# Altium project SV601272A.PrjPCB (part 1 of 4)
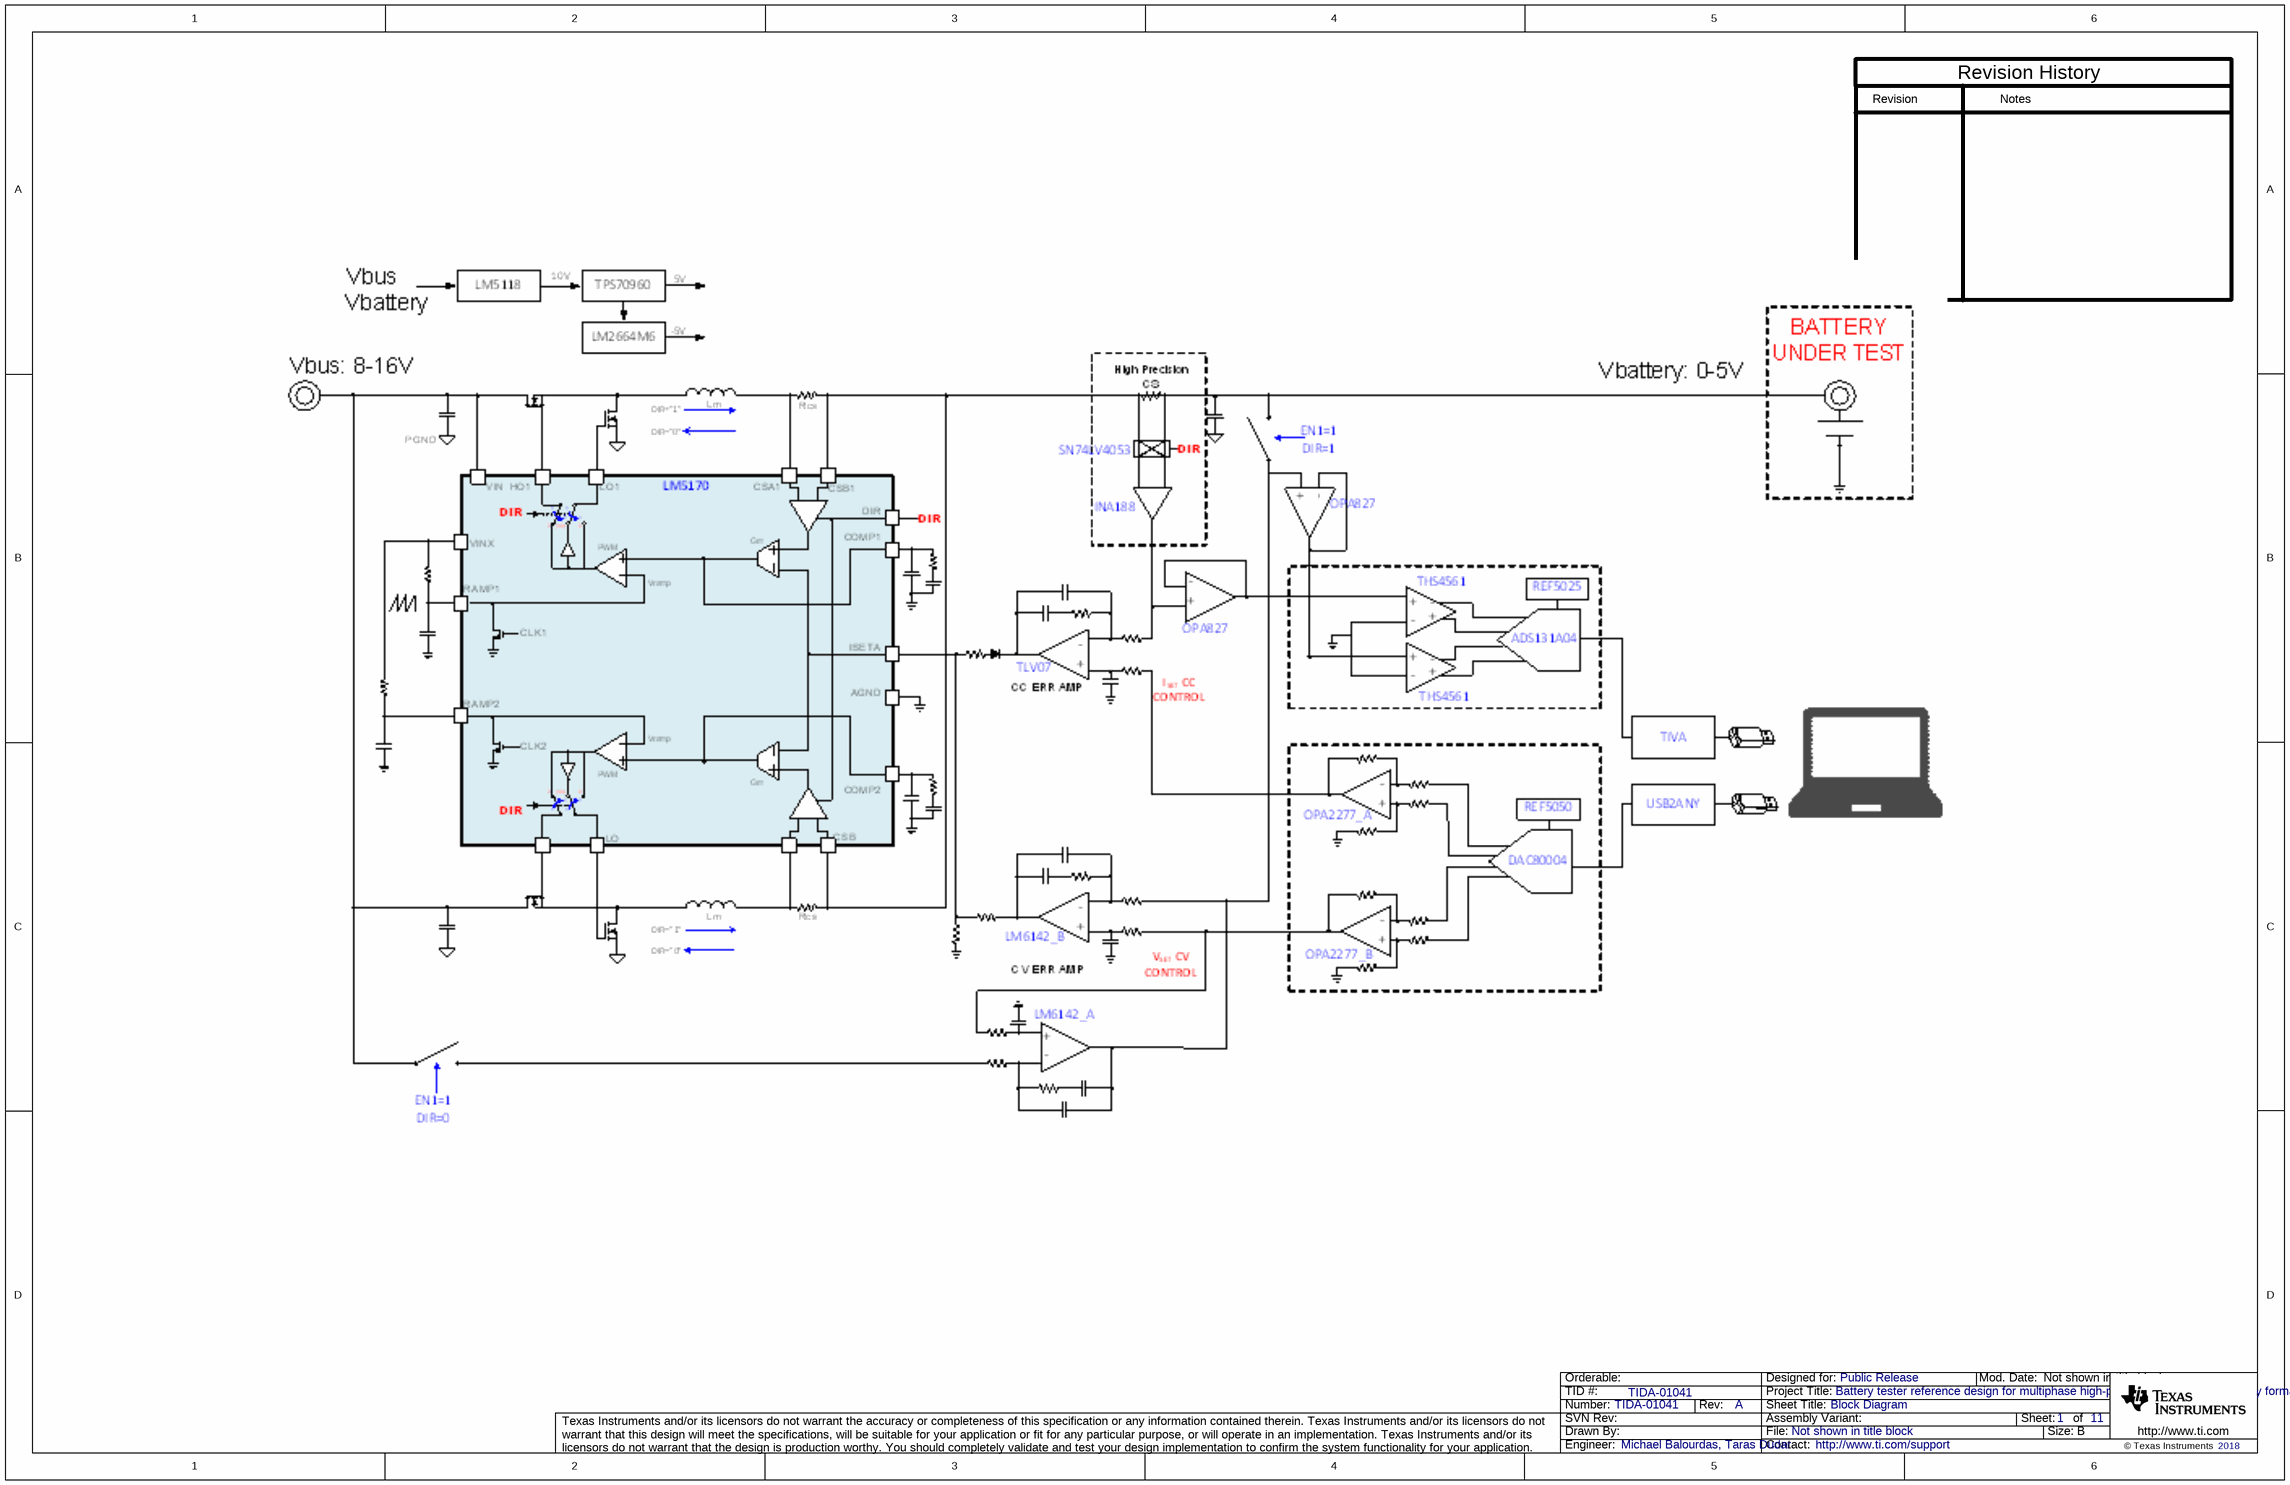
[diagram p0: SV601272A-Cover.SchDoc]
CopyrightYear: 2018; PCB_Layout: Dee Lim; PCB_Rev: A; PRJ_Customer: Public Release; PRJ_Engineer: Michael Balourdas, Taras Dudar; PRJ_Number: TIDA-01041; PRJ_Title: Battery tester reference design for multiphase high-precision 0.5 to 100-A battery formation; SCH_Rev: A; TechSupport: http://www.ti.com/support; TID: TIDA-01041
13 sheets, 552 parts. Net scope: flat (ports and power ports of the same name join across sheets).
Board file: SV601272A.PcbDoc
Sheets:
  SV601272A-Cover.SchDoc
  SV601272A-HW.SchDoc
  SV601272A-Analog.SchDoc
  SV601272A-DAC.SchDoc
  SV601272A-ADC.SchDoc
  SV601272A-TM4C_Main.SchDoc
  SV601272A-TM4C_Power.SchDoc
  SV601272A-Controller2.SchDoc
  SV601272A-Power2 REV2.SchDoc
  SV601272A-Controller1.SchDoc
  SV601272A-Bias.SchDoc
  SV601272A-Power.SchDoc
  SV601272A-Current-Control REV3.SchDoc

## Sheet SV601272A-Cover.SchDoc: Block Diagram
size 431 x 279 mm; Date: Not shown in title block; ApprovedBy: Not shown in title block; CheckedBy: Not shown in title block; Author: Not shown in title block; CompanyName: Not shown in title block; Engineer: Not shown in title block; Organization: Not shown in title block; Address1: Not shown in title block; Address2: Not shown in title block; Address3: Not shown in title block; Address4: Not shown in title block; DocumentNumber: 1; Revision: Use project parameter SCH_Rev; SheetNumber: 1; SheetTotal: 11; PageSetup: Record=PageOptions¦CenterHorizontal=True¦CenterVertical=True¦PrintScale=1.00¦XCorrection=1.00¦YCorrection=1.00¦PrintKind=0¦BorderSize=5000000¦LeftOffset=0¦BottomOffset=0¦Orientation=2¦PaperLength=1000¦PaperWidth=1000¦Scale=100¦PaperSource=15¦PrintQuality=600¦MediaType=1¦DitherType=10¦PaperKind=Letter¦PrintScaleMode=1

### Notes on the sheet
- Revision
- Notes
- Revision History

## Sheet SV601272A-HW.SchDoc: Hardware
size 431 x 279 mm; Date: Not shown in title block; ApprovedBy: Not shown in title block; CheckedBy: Not shown in title block; Author: Not shown in title block; CompanyName: Not shown in title block; Engineer: Not shown in title block; Organization: Not shown in title block; Address1: Not shown in title block; Address2: Not shown in title block; Address3: Not shown in title block; Address4: Not shown in title block; DocumentNumber: 2; Revision: Use project parameter SCH_Rev; SheetNumber: 2; SheetTotal: 11; PageSetup: Record=PageOptions¦CenterHorizontal=True¦CenterVertical=True¦PrintScale=1.00¦XCorrection=1.00¦YCorrection=1.00¦PrintKind=0¦BorderSize=5000000¦LeftOffset=0¦BottomOffset=0¦Orientation=2¦PaperLength=1000¦PaperWidth=1000¦Scale=100¦PaperSource=15¦PrintQuality=600¦MediaType=1¦DitherType=10¦PaperKind=Letter¦PrintScaleMode=1
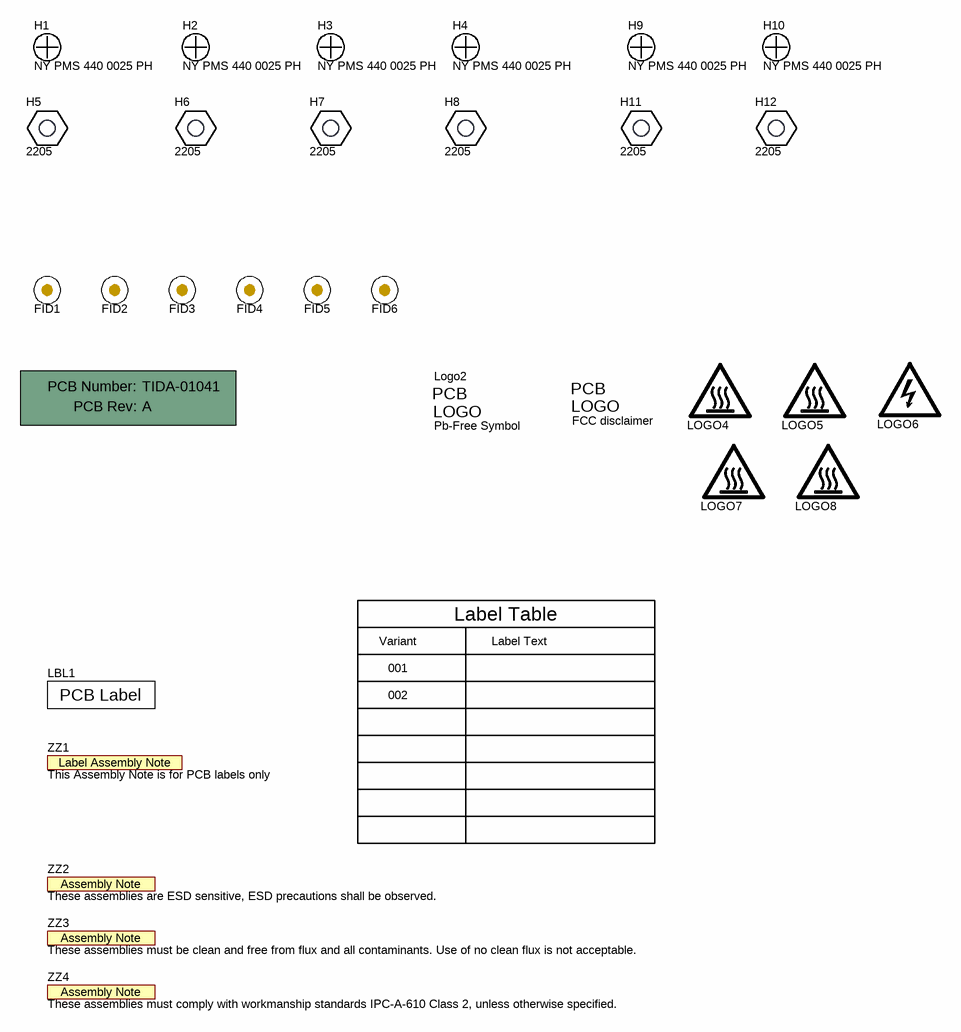
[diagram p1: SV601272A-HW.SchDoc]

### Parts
!PCB1  Printed Circuit Board  (value not drawn)  (mechanical)
FID1  Fiducial  [Fiducial10-20]  (value not drawn)
FID2  Fiducial  [Fiducial10-20]  (value not drawn)
FID3  Fiducial  [Fiducial10-20]  (value not drawn)
FID4  Fiducial  [Fiducial10-20]  (value not drawn)
FID5  Fiducial  [Fiducial10-20]  (value not drawn)
FID6  Fiducial  [Fiducial10-20]  (value not drawn)
H1  NY PMS 440 0025 PH  [NY PMS 440 0025 PH]
H2  NY PMS 440 0025 PH  [NY PMS 440 0025 PH]
H3  NY PMS 440 0025 PH  [NY PMS 440 0025 PH]
H4  NY PMS 440 0025 PH  [NY PMS 440 0025 PH]
H5  2205  [KEYSTONE_2205]
H6  2205  [KEYSTONE_2205]
H7  2205  [KEYSTONE_2205]
H8  2205  [KEYSTONE_2205]
H9  NY PMS 440 0025 PH  [NY PMS 440 0025 PH]
H10  NY PMS 440 0025 PH  [NY PMS 440 0025 PH]
H11  2205  [KEYSTONE_2205]
H12  2205  [KEYSTONE_2205]
LBL1  (no value)  [Label_1250x250]
Logo2  Pb-Free Symbol  [Pb-Free_Overlay_Medium]  (no BOM)
Logo3  FCC disclaimer  [FCC_disclaimer_stacked]  (no BOM)
LOGO4  CAUTION HOT SURFACE  [IEC_HotSurface_Small]  (value not drawn)  (no BOM)
LOGO5  CAUTION HOT SURFACE  [IEC_HotSurface_Small]  (value not drawn)  (no BOM)
LOGO6  DANGER HIGH VOLTAGE  [IEC_HighVoltage_Small]  (value not drawn)  (no BOM)
LOGO7  CAUTION HOT SURFACE  [IEC_HotSurface_Small]  (value not drawn)  (no BOM)
LOGO8  CAUTION HOT SURFACE  [IEC_HotSurface_Small]  (value not drawn)  (no BOM)
ZZ1  This Assembly Note is for PCB labels only  [AssemblyNoteLabel]  (no BOM)
ZZ2  These assemblies are ESD sensitive, ESD precautions shall be observed.  [AssemblyNote]  (no BOM)
ZZ3  These assemblies must be clean and free from flux and all contaminants. Use of no clean flux is not acceptable.  [AssemblyNote]  (no BOM)
ZZ4  These assemblies must comply with workmanship standards IPC-A-610 Class 2, unless otherwise specified.  [AssemblyNote]  (no BOM)

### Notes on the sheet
- Variant
- Label Table
- Label Text
- 001
- 002

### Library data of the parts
!PCB1 = PCB: Manufacturer: Any; PartNumber: TIDA-01041; SymbolCreator: a0412235
FID1-FID6 = Fiducial: Fiducial mark.  There is nothing to buy or mount.; SymbolCreator: codlsc
H1-H4 H9 H10 = NY PMS 440 0025 PH: Machine Screw, Round, #4-40 x 1/4, Nylon, Philips panhead; Manufacturer: B&F Fastener Supply; CompType: Hardware; SymbolCreator: codlsc; U/M: EA
H5-H8 H11 H12 = 2205: Standoff, Hex, 1"L #4-40 Aluminum; Manufacturer: Keystone; SymbolCreator: a0412235
LBL1 = THT-13-457-10: Thermal Transfer Printable Labels, 1.250" W x 0.250" H - 10,000 per roll; Manufacturer: Brady; SymbolCreator: a0412235; CompType: Label
Logo2 = Pb-Free: SymbolCreator: a0412235
Logo3 = FCC_disclaimer: SymbolCreator: codlsc
LOGO4 LOGO5 LOGO7 LOGO8 = IEC_HotSurface: IEC 61010-1 Hot Surface Warning; SymbolCreator: a0412235
LOGO6 = IEC_HighVoltage: IEC 61010-1 High Voltage Warning; SymbolCreator: a0412235
ZZ1 = AssemblyNoteLabel: SymbolCreator: a0412235
ZZ2-ZZ4 = AssemblyNote: SymbolCreator: codlsc

## Sheet SV601272A-Analog.SchDoc: Analog Loop Controller
size 431 x 279 mm; Date: Not shown in title block; ApprovedBy: Not shown in title block; CheckedBy: Not shown in title block; Author: Not shown in title block; CompanyName: Not shown in title block; Engineer: Not shown in title block; Organization: Not shown in title block; Address1: Not shown in title block; Address2: Not shown in title block; Address3: Not shown in title block; Address4: Not shown in title block; DocumentNumber: 7; Revision: Use project parameter SCH_Rev; SheetNumber: 7; SheetTotal: 11; PageSetup: Record=PageOptions¦CenterHorizontal=True¦CenterVertical=True¦PrintScale=1.00¦XCorrection=1.00¦YCorrection=1.00¦PrintKind=0¦BorderSize=5000000¦LeftOffset=0¦BottomOffset=0¦Orientation=2¦PaperLength=1000¦PaperWidth=1000¦Scale=100¦PaperSource=15¦PrintQuality=600¦MediaType=1¦DitherType=10¦PaperKind=Letter¦PrintScaleMode=1
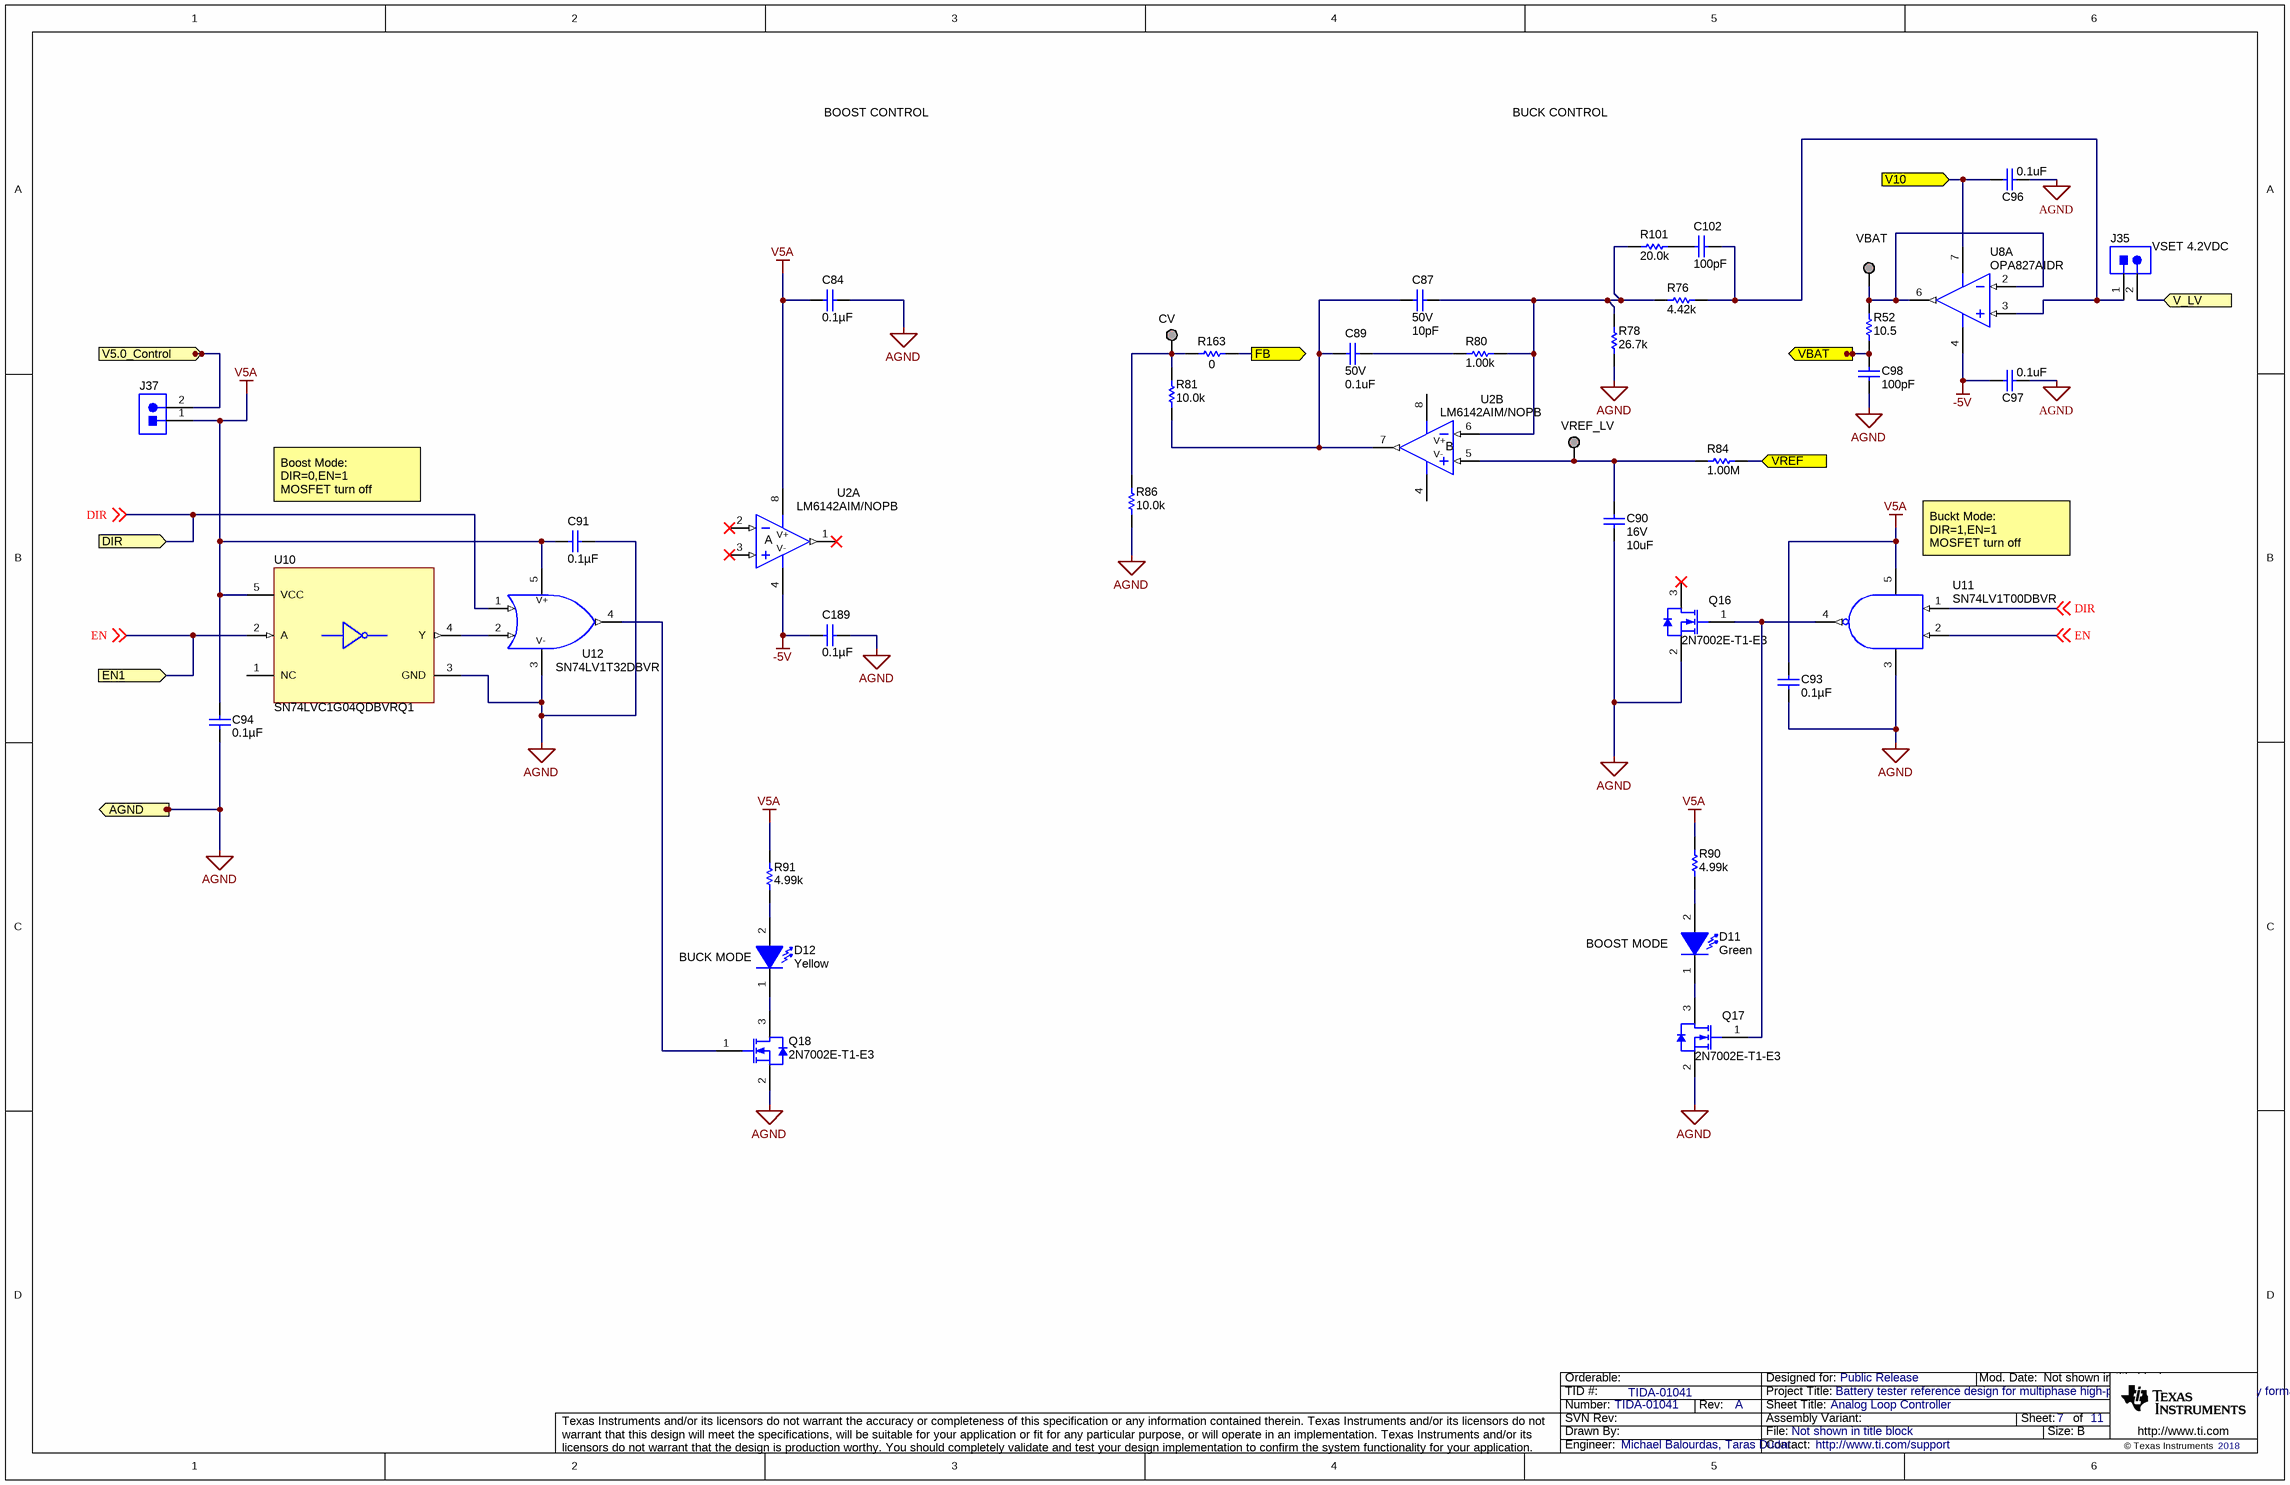
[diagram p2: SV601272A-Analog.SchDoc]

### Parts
C84  ValueDisplayed: 0.1µF  [0603L]  (hidden comment: GRM188R72A104KA35D)
C87  VDC_V: 50V  ValueDisplayed: 10pF  [0603]  (hidden comment: C0603C100J5GACTU)
C89  VDC_V: 50V  ValueDisplayed: 0.1uF  [0603]  (hidden comment: C1608X5R1H104K080AA)
C90  VDC_V: 16V  ValueDisplayed: 10uF  [0603]  (hidden comment: EMK107BBJ106MA-T)
C91  ValueDisplayed: 0.1µF  [0603L]  (hidden comment: GRM188R72A104KA35D)
C93  ValueDisplayed: 0.1µF  [0603L]  (hidden comment: GRM188R72A104KA35D)
C94  ValueDisplayed: 0.1µF  [0603L]  (hidden comment: GRM188R72A104KA35D)
C96  ValueDisplayed: 0.1uF  [0603]  (hidden comment: Capacitor)
C97  ValueDisplayed: 0.1uF  [0603]  (hidden comment: Capacitor)
C98  ValueDisplayed: 100pF  [0603L]  (hidden comment: Capacitor)
C102  ValueDisplayed: 100pF  [0603L]  (hidden comment: C0603C101J5GACTU)
C189  ValueDisplayed: 0.1µF  [0603L]  (hidden comment: GRM188R72A104KA35D)
CV  Pogo Pad  [PogoPad]  (value not drawn)  (no BOM)
D11  value Green  [WL-SMCW_GREEN]  (hidden comment: 150060VS75000)
D12  value Yellow  [WL-SMCW_YELLOW]  (hidden comment: 150060YS75000)
J35  HTSW-102-07-G-S  [Samtec_HTSW-102-07-G-S]  (value not drawn)
J37  HTSW-102-07-G-S  [Samtec_HTSW-102-07-G-S]  (value not drawn)
Q16  2N7002E-T1-E3  [SOT-23]
Q17  2N7002E-T1-E3  [SOT-23]
Q18  2N7002E-T1-E3  [SOT-23]
R52  ValueDisplayed: 10.5  [0603]  (hidden comment: RC0603FR-0710R5L)
R76  ValueDisplayed: 4.42k  [0603L]  (hidden comment: CRCW06034K42FKEA)
R78  ValueDisplayed: 26.7k  [0603L]  (hidden comment: CRCW060326K7FKEA)
R80  ValueDisplayed: 1.00k  [0603]  (hidden comment: CRCW06031K00FKEA)
R81  ValueDisplayed: 10.0k  [0603L]  (hidden comment: CRCW060310K0FKEA)
R84  ValueDisplayed: 1.00M  [0603]  (hidden comment: MCT06030C1004FP500)
R86  ValueDisplayed: 10.0k  [0603L]  (hidden comment: CRCW060310K0FKEA)
R90  ValueDisplayed: 4.99k  [0603L]  (hidden comment: CRCW06034K99FKEA)
R91  ValueDisplayed: 4.99k  [0603L]  (hidden comment: CRCW06034K99FKEA)
R101  ValueDisplayed: 20.0k  [0603L]  (hidden comment: CRCW060320K0FKEA)
R163  ValueDisplayed: 0  [0603]  (hidden comment: Resistor)
U2  LM6142AIM/NOPB  [D0008A_N]  (parts A,B of 2)
U8  OPA827AIDR  [D0008A_L]  (part A of 2)
U10  SN74LVC1G04QDBVRQ1  [DBV0005A_N]
U11  SN74LV1T00DBVR  [DBV0005A_N]
U12  SN74LV1T32DBVR  [DBV0005A_N]
VBAT  Pogo Pad  [PogoPad]  (value not drawn)  (no BOM)
VREF_LV  Pogo Pad  [PogoPad]  (value not drawn)  (no BOM)

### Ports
AGND, DIR, EN1, FB, V5.0_Control, V10, V_LV, VBAT, VREF

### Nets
-5V: C97.1 C189.1 U2.4(V-) U8.4(V-)
AGND: C84.2 C90.2 C91.1 C93.2 C94.1 C96.2 C97.2 C98.2 C189.2 Q16.2(S) Q17.2(S) Q18.2(S) R78.1 R86.2 U10.3(GND) U11.3(GND) U12.3(GND) ; port AGND
V5A: C84.1 C91.2 C93.1 C94.2 J37.1 R90.1 R91.1 U2.8(V+) U10.5(VCC) U11.5(VCC) U12.5(VCC)
V_LV: J35.2 ; port V_LV
VCC: C96.1 U8.7(V+) ; port V10
DIR: U11.1(A) U12.1(A) ; off-sheet DIR, port DIR
EN: U10.2(A) U11.2(B) ; off-sheet EN, port EN1
FB: R163.2 ; port FB
V5.0_Control: J37.2 ; port V5.0_Control
VBAT: C98.1 R52.1 ; port VBAT
VREF: R84.2 ; port VREF
NetC87_1: C87.1 R76.2 R78.2 R80.2 R101.2 U2.6(IN-)
NetC87_2: C87.2 C89.2 R81.2 U2.7(OUT)
NetC89_1: C89.1 R80.1
NetC90_1: C90.1 R84.1 U2.5(IN+) VREF_LV.1
NetC102_1: C102.1 J35.1 R76.1 U8.3(IN+)
NetC102_2: C102.2 R101.1
NetCV_1: CV.1 R81.1 R86.1 R163.1
NetD11_1: D11.1(K) Q17.3(D)
NetD11_2: D11.2(A) R90.2
NetD12_1: D12.1(K) Q18.3(D)
NetD12_2: D12.2(A) R91.2
NetQ16_1: Q16.1(G) Q17.1(G) U11.4(Y)
NetQ18_1: Q18.1(G) U12.4(Y)
NetR52_2: R52.2 U8.2(IN-) U8.6(OUT) VBAT.1
NetU10_4: U10.4(Y) U12.2(B)

Not connected (* = marked no-connect by the designer): Q16 3(D)*; U2 1(OUT)* 2(IN-)* 3(IN+)*; U10 1(NC)

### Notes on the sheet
- BOOST CONTROL
- BUCK CONTROL
- (near J35) VSET 4.2VDC
- Boost Mode: DIR=0,EN=1
  MOSFET turn off
- (near U11) Buckt Mode: DIR=1,EN=1
  MOSFET turn off
- (near D12) BUCK MODE
- (near D11) BOOST MODE

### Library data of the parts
C84 C91 C93 C94 C189 = GRM188R72A104KA35D: CAP, CERM, 0.1 µF, 100 V, +/- 10%, X7R, 0603; Manufacturer: MuRata; Polarized: N; CompType: Capacitor; Value: 0.1uF; U/M: EA; Cap_F: 0.0000001; Tolerance_%: 10; Value1: Unknown; VDC_V: 100; Value2: 100V; TaMin_C: -55; TaMax_C: 125; Cap_Case: 0603; AEC Category: Q200
C87 = CMP-0006839-4: CAP, CERM, 10 pF, 50 V, +/- 5%, C0G/NP0, 0603; Manufacturer: Kemet; TaMin_C: -55°C; Polarized: N; SizeAreaWB_mm2: 4.68; Value1: Unknown; U/M: EA; Value: 10pF; TaMax_C: 125°C; SizeZ_mm: 1; SizeX_mm: 1.6; SizeY_mm: 0.8; SizeArea_mm2: 1.28; CompType: Capacitor; AEC Category: Q200
C89 = CMP-0007010-5: CAP, CERM, 0.1 uF, 50 V, +/- 10%, X5R, 0603; Manufacturer: TDK; TaMin_C: -55°C; ESR_ohm: 0.0296; Polarized: N; SizeAreaWB_mm2: 4.68; Value1: 0.0296 ohm; U/M: EA; Value: 0.1uF; TaMax_C: 85°C; SizeZ_mm: 1; SizeX_mm: 1.6; SizeY_mm: 0.8; SizeArea_mm2: 1.28; CompType: Capacitor; Cap_F: 100nF; IRMS_A: 9.7199dA; AEC Category: Q200
C90 = CMP-0007122-5: CAP, CERM, 10 uF, 16 V, +/- 20%, X5R, 0603; Manufacturer: Taiyo Yuden; TaMin_C: -55°C; Polarized: N; SizeAreaWB_mm2: 4.68; Value1: Unknown; U/M: EA; Value: 10uF; TaMax_C: 85°C; SizeZ_mm: 1; SizeX_mm: 1.6; SizeY_mm: 0.8; SizeArea_mm2: 1.28; CompType: Capacitor; Cap_F: 10µF; AEC Category: Q200
C96 C97 = CMP-0006752-5: CAP, CERM, 0.1 uF, 25 V, +/- 5%, X7R, 0603; PartNumber: 06033C104JAT2A; Manufacturer: AVX; Polarized: N; Value: 0.1uF; U/M: EA; Cap_F: 100nF; ESR_ohm: 0.05; Value1: 0.05 ohm; VDC_V: 25V; TaMin_C: -55°C; TaMax_C: 125°C; AEC Category: Q200; SizeArea_mm2: 1.28; SizeAreaWB_mm2: 4.68; SizeX_mm: 1.6; SizeY_mm: 0.8; SizeZ_mm: 1
C98 = CMP-0006841-4: CAP, CERM, 100 pF, 50 V, +/- 5%, C0G/NP0, 0603; PartNumber: C0603C101J5GACTU; Manufacturer: Kemet; Polarized: N; Value: 100pF; U/M: EA; Value1: Unknown; VDC_V: 50V; TaMin_C: -55°C; TaMax_C: 125°C; Cap_Case: 0603; AEC Category: Q200; SizeArea_mm2: 1.28; SizeAreaWB_mm2: 4.68; SizeX_mm: 1.6; SizeY_mm: 0.8; SizeZ_mm: 1
C102 = C0603C101J5GACTU: CAP, CERM, 100 pF, 50 V, +/- 5%, C0G/NP0, 0603; Manufacturer: Kemet; Polarized: N; CompType: Capacitor; Value: 100pF; U/M: EA; Cap_F: 0.0000000001; Tolerance_%: 5; Value1: Unknown; VDC_V: 50; Value2: 50V; TaMin_C: -55; TaMax_C: 125; Cap_Case: 0603
CV VBAT VREF_LV = PogoPad: Pad for Pogo Pin Connector; SymbolCreator: codlsc
D11 = 150060VS75000: LED, Green, SMD; Manufacturer: Wurth Elektronik; Type: AlInGaP; Vf_V: 2; Value2: 2V; Io_A: 0.02; Value1: W; U/M: EA
D12 = 150060YS75000: LED, Yellow, SMD; Manufacturer: Wurth Elektronik; Type: AlInGaP; Vf_V: 2; Value2: 2V; Io_A: 0.02; Value1: W; U/M: EA
J35 J37 = HTSW-102-07-G-S: Header, 100mil, 2x1, Gold, TH; Manufacturer: Samtec; SymbolCreator: a0412235; U/M: EA
Q16-Q18 = 2N7002E-T1-E3: MOSFET, N-CH, 60 V, 0.24 A, SOT-23; Manufacturer: Vishay-Siliconix; Alternate Manufacturer: None; U/M: EA; ChType: N; Value: 60V; VdsMax_V: 60; Value1: 1.8 ohm; Rdson45_ohm: 1.8; Value2: 0.4 nC; QgTyp_nC: 0.4; Vgs_V: 20; IdsMax_A: 0.24
R52 = CMP-0022749-2: RES, 10.5, 1%, 0.1 W, 0603; Manufacturer: Yageo America; Power_W: 100mW; TempCo: 200 ppm/C; Value_Code: 10R5; U/M: EA; Value: 10.5; EIA_Code: E96; SizeX_mm: 1.6; SizeY_mm: 0.8; SizeZ_mm: 1; Value2: 0.1W; SizeArea_mm2: 1.28; CompType: Resistor; VDC_V: 150V; AEC Category: Q200
R76 = CRCW06034K42FKEA: RES, 4.42 k, 1%, 0.1 W, 0603; Manufacturer: Vishay-Dale; CompType: Resistor; Value: 4.42k; Res_ohm: 4420; Value_Code: 4k42; Tolerance_%: 1; Power_W: 0.1; Value2: 0.1W; VDC_V: 75; TempCo: 100 ppm/C; EIA_Code: E96; U/M: EA; AEC Category: Q200; SizeArea_mm2: 1.28; SizeX_mm: 1.6; SizeY_mm: 0.8
R78 = CRCW060326K7FKEA: RES, 26.7 k, 1%, 0.1 W, 0603; Manufacturer: Vishay-Dale; CompType: Resistor; Value: 26.7k; Res_ohm: 26700; Value_Code: 26k7; Tolerance_%: 1; Power_W: 0.1; Value2: 0.1W; VDC_V: 75; TempCo: 100 ppm/C; EIA_Code: E96; U/M: EA; AEC Category: Q200; SizeArea_mm2: 1.28; SizeX_mm: 1.6; SizeY_mm: 0.8
R80 = CMP-0022109-5: RES, 1.00 k, 1%, 0.1 W, AEC-Q200 Grade 0, 0603; Manufacturer: Vishay-Dale; Power_W: 100mW; TempCo: 100 ppm/C; Value_Code: 1k00; Value: 1.00k; EIA_Code: E96; Res_ohm: 1k; SizeX_mm: 1.6; SizeY_mm: 0.8; SizeZ_mm: 1; Value2: 0.1W; SizeArea_mm2: 1.28; CompType: Resistor; AEC Qualified: Y; VDC_V: 75V; AEC Category: Q200; AEC Grade: 0
R81 R86 = CRCW060310K0FKEA: RES, 10.0 k, 1%, 0.1 W, 0603; Manufacturer: Vishay-Dale; CompType: Resistor; Value: 10.0k; Res_ohm: 10000; Value_Code: 10k0; Tolerance_%: 1; Power_W: 0.1; Value2: 0.1W; VDC_V: 75; TempCo: 100 ppm/C; EIA_Code: E96; U/M: EA
R84 = CMP-0022731-2: RES, 1.00 M, 1%, 0.125 W, 0603; Manufacturer: Vishay/Beyschlag; Power_W: 125mW; TempCo: 50 ppm/C; Value_Code: 1M00; U/M: EA; Value: 1.00Meg; EIA_Code: E96; Res_ohm: 1M; SizeX_mm: 1.6; SizeY_mm: 0.8; SizeZ_mm: 1; Value2: 0.125W; SizeArea_mm2: 1.28; CompType: Resistor; AEC Qualified: N; VDC_V: 75V; AEC Category: Q200
R90 R91 = CRCW06034K99FKEA: RES, 4.99 k, 1%, 0.1 W, 0603; Manufacturer: Vishay-Dale; CompType: Resistor; Value: 4.99k; Res_ohm: 4990; Value_Code: 4k99; Tolerance_%: 1; Power_W: 0.1; Value2: 0.1W; VDC_V: 75; TempCo: 100 ppm/C; EIA_Code: E96; U/M: EA
R101 = CRCW060320K0FKEA: RES, 20.0 k, 1%, 0.1 W, 0603; Manufacturer: Vishay-Dale; CompType: Resistor; Value: 20.0k; Res_ohm: 20000; Value_Code: 20k0; Tolerance_%: 1; Power_W: 0.1; Value2: 0.1W; VDC_V: 75; TempCo: 100 ppm/C; EIA_Code: E96; U/M: EA; SizeArea_mm2: 1.28; SizeX_mm: 1.6; SizeY_mm: 0.8; AEC Category: Q200
R163 = CMP-0025874-3: RES, 0, 5%, 0.1 W, 0603; PartNumber: ERJ-3GEY0R00V; Manufacturer: Panasonic; Value: 0; Value_Code: 0000; Power_W: 100mW; Value2: 0.1W; VDC_V: 50V; TempCo: 600 ppm/C; EIA_Code: E24; U/M: EA; AEC Category: Q200; SizeArea_mm2: 1.28; SizeX_mm: 1.6; SizeY_mm: 0.8; SizeZ_mm: 1
U2 = LM6142AIM: 17MHz Rail-to-Rail Input and Output Op Amp, D0008A; Manufacturer: Texas Instruments; CompType: OpAmp IC
U8 = CMP-0041267-2: Low-Noise, High-Precision, JFET-Input Operational Amplifier, 8 to 36 V, -40 to 125 degC, 8-pin SOIC (D8), Green (RoHS & no Sb/Br); Manufacturer: Texas Instruments; Vmax(V): 36; GBW(Typ)(MHz): 22; Vmin(V): 8; Iq per channel(Max)(mA): 5.2; SubFamily: Audio Operational Amplifier; Number of Channels: 1; Vn at Flatband(Typ)(nV/rtHz): 4
U10 = SN74LVC1G04QDBVRQ1: Single Inverter Gate, DBV0005A; Manufacturer: Texas Instruments; SymbolCreator: a0411947; CompType: IC; U/M: EA
U11 = SN74LV1T00DBVR: Single Power Supply 2-Input Positive NAND Gate CMOS Logic Level Shifter, DBV0005A; Manufacturer: Texas Instruments; SymbolCreator: a0411947; CompType: IC; U/M: EA
U12 = SN74LV1T32DBVR: Single Power Supply 2-Input Positive OR Gate CMOS Logic Level Shifter, DBV0005A; Manufacturer: Texas Instruments; SymbolCreator: a0411947; CompType: IC; U/M: EA

## Sheet SV601272A-DAC.SchDoc
size 431 x 279 mm; Date: Not shown in title block; ApprovedBy: Not shown in title block; CheckedBy: Not shown in title block; Author: Not shown in title block; CompanyName: Not shown in title block; Engineer: Not shown in title block; Organization: Not shown in title block; Address1: Not shown in title block; Address2: Not shown in title block; Address3: Not shown in title block; Address4: Not shown in title block; DocumentNumber: 8; Revision: Use project parameter SCH_Rev; SheetNumber: 8; SheetTotal: 11; PageSetup: Record=PageOptions¦CenterHorizontal=True¦CenterVertical=True¦PrintScale=1.00¦XCorrection=1.00¦YCorrection=1.00¦PrintKind=0¦BorderSize=5000000¦LeftOffset=0¦BottomOffset=0¦Orientation=2¦PaperLength=1000¦PaperWidth=1000¦Scale=100¦PaperSource=15¦PrintQuality=600¦MediaType=1¦DitherType=10¦PaperKind=Letter¦PrintScaleMode=1
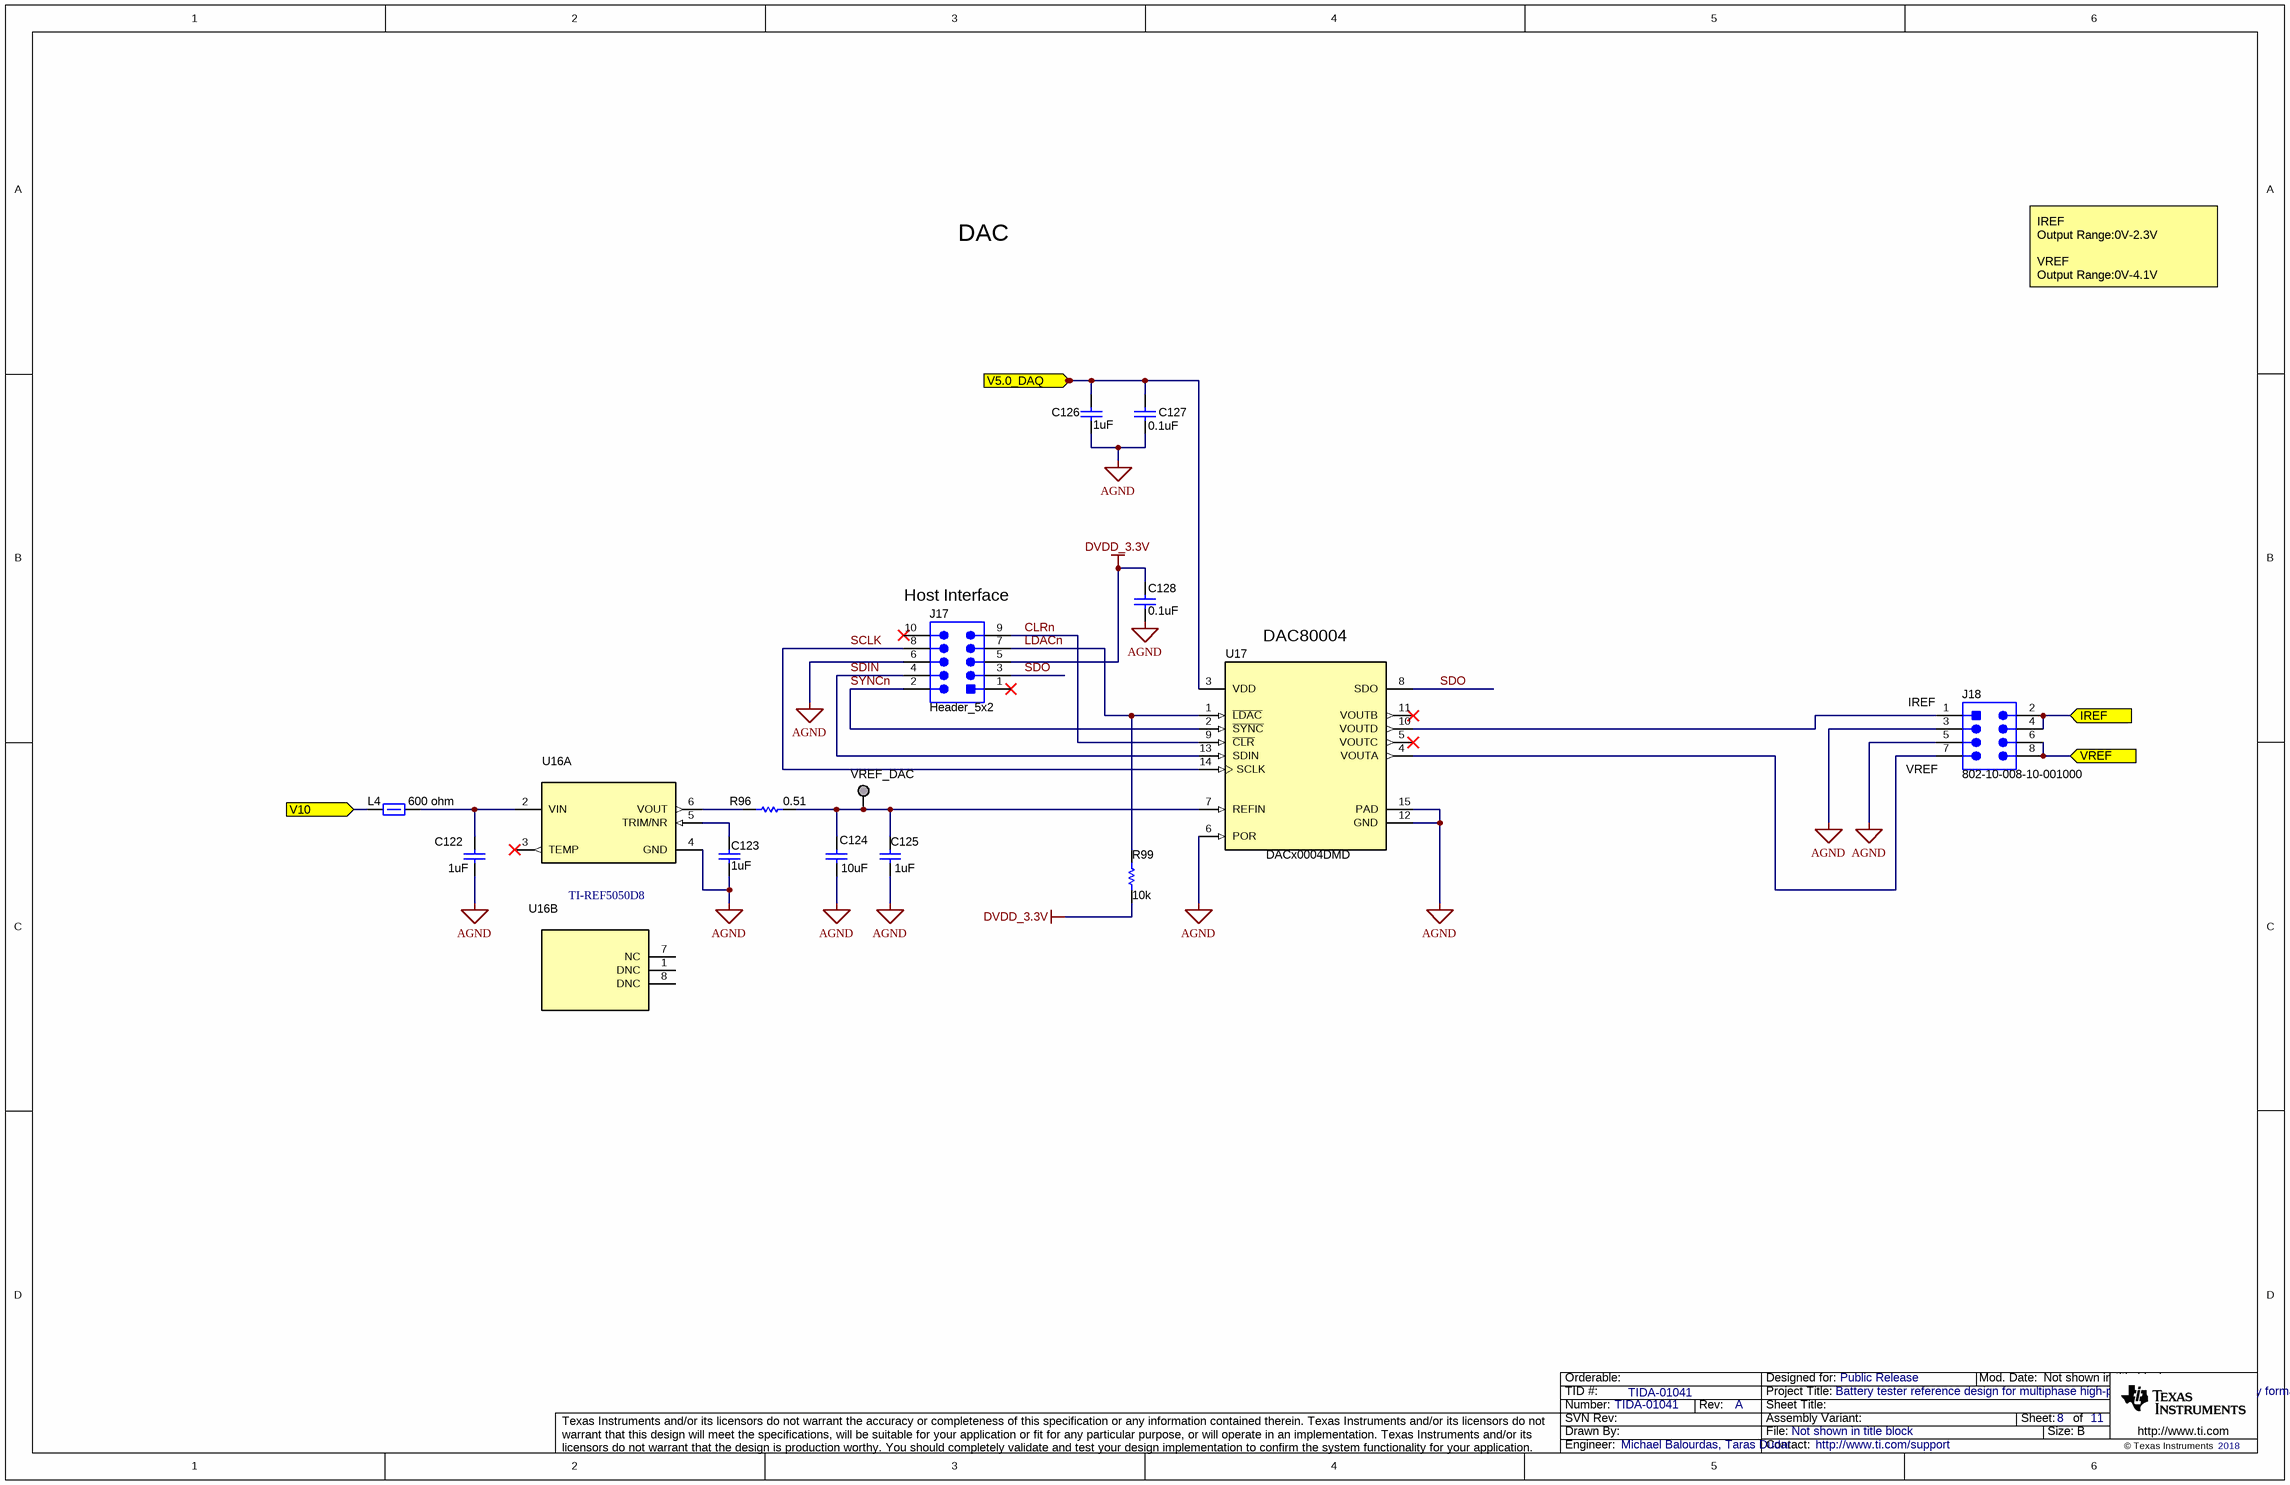
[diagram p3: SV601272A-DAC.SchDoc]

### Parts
C122  ValueDisplayed: 1uF  [1206]  (hidden comment: Capacitor)
C123  ValueDisplayed: 1uF  [1206]  (hidden comment: Capacitor)
C124  ValueDisplayed: 10uF  [0805_HV]  (hidden comment: Capacitor)
C125  ValueDisplayed: 1uF  [1206]  (hidden comment: Capacitor)
C126  ValueDisplayed: 1uF  [1206]  (hidden comment: Capacitor)
C127  ValueDisplayed: 0.1uF  [0603]  (hidden comment: Capacitor)
C128  ValueDisplayed: 0.1uF  [0603]  (hidden comment: Capacitor)
J17  Header_5x2  [Assman_AWHW-10G-0x02-T]
J18  802-10-008-10-001000  [Mill-Max_802-10-008-10-001000]
L4  value 600 ohm  [0603]  (hidden comment: Ferrite_Bead)
R96  ValueDisplayed: 0.51  [0603]  (hidden comment: Resistor)
R99  ValueDisplayed: 10k  [0603]  (hidden comment: Resistor)
U16  TI-REF5050D8  [D0008A_N]  (parts A,B of 2)
U17  DACx0004DMD  [DMD0014A]
VREF_DAC  Pogo Pad  [PogoPad]  (value not drawn)  (no BOM)

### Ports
IREF, V5.0_DAQ, V10, VREF

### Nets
AGND: C122.2 C123.2 C124.2 C125.2 C126.2 C127.2 C128.2 J17.6 J18.3 J18.5 U16.4(GND) U17.6(POR) U17.12(GND) U17.15(PAD)
AVDD: C126.1 C127.1 U17.3(VDD) ; port V5.0_DAQ
DVDD_3.3V: C128.1 J17.5 R99.1
VCC: L4.1 ; port V10
CLRn: J17.9 U17.9(~{CLR})
IREF: J18.2 J18.4 ; port IREF
LDACn: J17.7 R99.2 U17.1(~{LDAC})
SCLK: J17.8 U17.14(SCLK)
SDIN: J17.4 U17.13(SDIN)
SDO: J17.3 U17.8(SDO)
SYNCn: J17.2 U17.2(~{SYNC})
VREF: J18.6 J18.8 ; port VREF
NetC122_1: C122.1 L4.2 U16.2(VIN)
NetC123_1: C123.1 U16.5(TRIM/NR)
NetC124_1: C124.1 C125.1 R96.2 U17.7(REFIN) VREF_DAC.1
NetJ18_1: J18.1 U17.10(VOUTD)
NetJ18_7: J18.7 U17.4(VOUTA)
NetR96_1: R96.1 U16.6(VOUT)

Not connected (* = marked no-connect by the designer): J17 1* 10*; U16 1(DNC) 3(TEMP)* 7(NC) 8(DNC); U17 5(VOUTC)* 11(VOUTB)*

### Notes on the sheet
- DAC
- IREF
  Output Range:0V-2.3V
  VREF
  Output Range:0V-4.1V
- (near J17) Host Interface
- (near U17) DAC80004
- (near J18) IREF
- (near J18) VREF

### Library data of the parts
C122 C123 C125 C126 = CMP-0008509-2: CAP, CERM, 1 uF, 25 V, +/- 10%, X7R, 1206; PartNumber: 12063C105KAT2A; Manufacturer: AVX; Polarized: N; Value: 1uF; U/M: EA; Cap_F: 1µF; ESR_ohm: 0.013; Value1: 0.013 ohm; VDC_V: 25V; TaMin_C: -55°C; TaMax_C: 125°C; SizeArea_mm2: 5.12; SizeAreaWB_mm2: 10.92; SizeX_mm: 3.2; SizeY_mm: 1.6; SizeZ_mm: 1.35; AEC Category: Q200
C124 = CMP-0008273-1: CAP, CERM, 10 uF, 35 V, +/- 10%, X6S, 0805; PartNumber: GRM21BC8YA106KE11L; Manufacturer: MuRata; Polarized: N; Value: 10uF; U/M: EA; Cap_F: 10µF; Value1: Unknown; VDC_V: 35V; TaMin_C: -55°C; TaMax_C: 105°C; Cap_Case: 0805; SizeArea_mm2: 2.5; SizeAreaWB_mm2: 6.75; SizeX_mm: 2; SizeY_mm: 1.25; SizeZ_mm: 1.45; AEC Category: Q200
C127 C128 = CMP-0006857-4: CAP, CERM, 0.1 uF, 16 V, +/- 5%, X7R, 0603; PartNumber: C0603C104J4RACTU; Manufacturer: Kemet; Polarized: N; Value: 0.1uF; U/M: EA; Cap_F: 100nF; Value1: Unknown; VDC_V: 16V; TaMin_C: -55°C; TaMax_C: 125°C; SizeArea_mm2: 1.28; SizeAreaWB_mm2: 4.68; SizeX_mm: 1.6; SizeY_mm: 0.8; SizeZ_mm: 1; AEC Category: Q200
J17 = CMP-0075161-1: Header(Shrouded), 2.54mm, 5x2, Gold, TH; PartNumber: AWHW-10G-0202-T; Manufacturer: Assman WSW; Pitch_mm: 2.54; Gender: Male; Shrouded: Y; Row_Count: 2; CNHeader: False; Green_Lifecycle: Active; Green_REACh: Passed
J18 = CMP-0055096-1: Header, 2.54 mm, 4x2, Gold, TH; Manufacturer: Mill-Max; CNHeader: TRUE; Shrouded: N; Gender: Male; Row_Count: 2; RowSpacing_mm: 2.54; CT: FALSE
L4 = CMP-0003197-2: Ferrite Bead, 600 ohm @ 100 MHz, 1 A, 0603; PartNumber: 742792651; Manufacturer: Wurth Elektronik; Imax_A: 1A; DCR_ohm: 2d; Value1: 0.2 ohm; ZTyp@100MHz_Ohm: 600; Ztyp@1GHz_Ohm: 257.548; SizeArea_mm2: 1.28; SizeAreaWB_mm2: 4.68; SizeX_mm: 1.6; SizeY_mm: 0.8; SizeZ_mm: 1
R96 = CMP-0022717-2: RES, 0.51, 1%, 0.1 W, AEC-Q200 Grade 1, 0603; PartNumber: ERJ-3RQFR51V; Manufacturer: Panasonic; Value: 0.51; Res_ohm: 5.1d; Value_Code: R510; Power_W: 100mW; Value2: 0.1W; TempCo: 300 ppm/C; SizeArea_mm2: 1.28; SizeX_mm: 1.6; SizeY_mm: 0.8; SizeZ_mm: 1; EIA_Code: E96; U/M: EA; AEC Category: Q200; AEC Qualified: Y
R99 = CMP-0025701-4: RES, 10 k, 5%, 0.1 W, AEC-Q200 Grade 0, 0603; PartNumber: CRCW060310K0JNEA; Manufacturer: Vishay-Dale; Value: 10k; Value_Code: 10k0; Power_W: 100mW; Value2: 0.1W; VDC_V: 75V; TempCo: 200 ppm/C; SizeArea_mm2: 1.28; SizeX_mm: 1.6; SizeY_mm: 0.8; SizeZ_mm: 1; EIA_Code: E24; AEC Category: Q200; AEC Qualified: Y; AEC Grade: 0
U16 = CMP-0032617-1: Low Noise, Very Low Drift, Precision Voltage Reference, -40 to 125 degC, 8-pin SOIC (D), Green (RoHS & no Sb/Br); PartNumber: REF5050AID; Manufacturer: Texas Instruments; Initial Accuracy @ 25/deg C(%): 0.05; Iout/Iz(Max)(mA): 10; Iq(Max)(uA): 1000; Rating: Catalog; SubFamily: Series Voltage Reference; Temp Coeff(Max)(ppm/ degree C): 3; VI(Max)(V): 18; VI(Min)(V): 5.2; VO(V): 5
U17 = CMP-0013342-2: QUAD 16-BIT, 1LSB INL, BUFFERED, VOLTAGE-OUTPUT DIGITAL-to-ANALOG CONVERTERS, DMD0014A (VSON-14); PartNumber: DAC80004IDMD; Manufacturer: Texas Instruments; SizeArea_mm2: 12; SizeAreaWB_mm2: 20; SizeX_mm: 3; SizeY_mm: 4; SizeZ_mm: 1; CompType: IC; U/M: EA
VREF_DAC = PogoPad: as CV on sheet SV601272A-Analog

## Sheet SV601272A-ADC.SchDoc
size 431 x 279 mm; Date: Not shown in title block; ApprovedBy: Not shown in title block; CheckedBy: Not shown in title block; Author: Not shown in title block; CompanyName: Not shown in title block; Engineer: Not shown in title block; Organization: Not shown in title block; Address1: Not shown in title block; Address2: Not shown in title block; Address3: Not shown in title block; Address4: Not shown in title block; DocumentNumber: 9; Revision: Use project parameter SCH_Rev; SheetNumber: 9; SheetTotal: 11; PageSetup: Record=PageOptions¦CenterHorizontal=True¦CenterVertical=True¦PrintScale=1.00¦XCorrection=1.00¦YCorrection=1.00¦PrintKind=0¦BorderSize=5000000¦LeftOffset=0¦BottomOffset=0¦Orientation=2¦PaperLength=1000¦PaperWidth=1000¦Scale=100¦PaperSource=15¦PrintQuality=600¦MediaType=1¦DitherType=10¦PaperKind=Letter¦PrintScaleMode=1
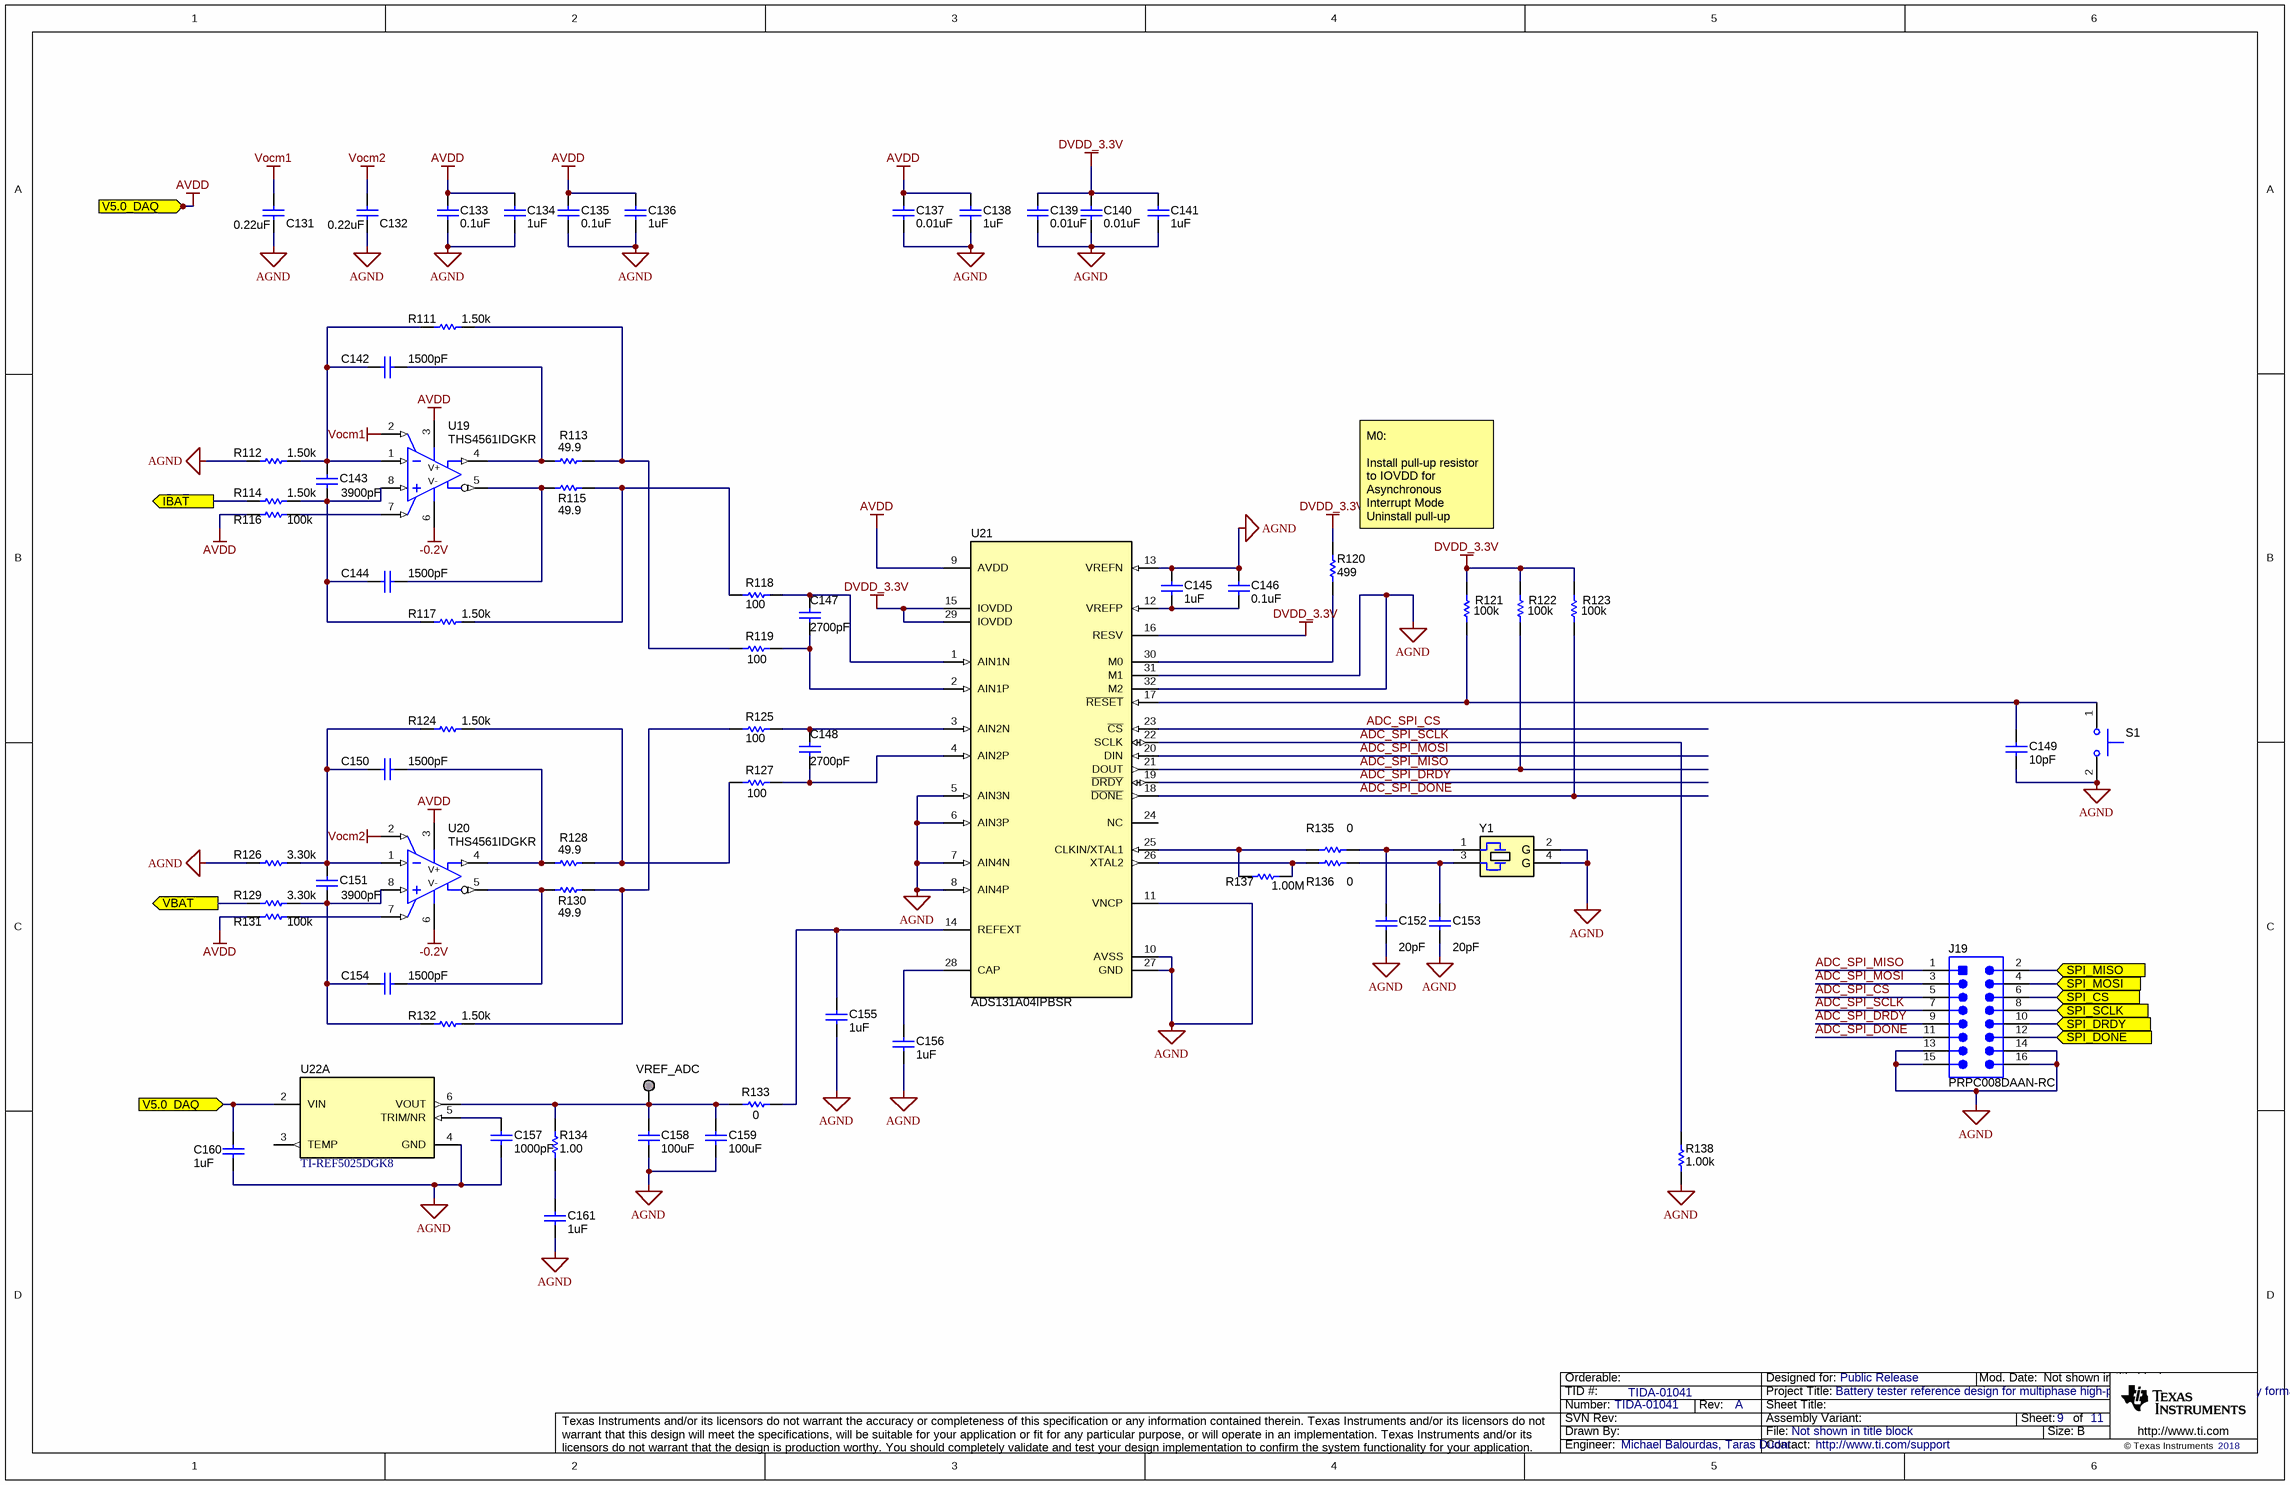
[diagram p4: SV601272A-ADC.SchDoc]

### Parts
C131  ValueDisplayed: 0.22uF  [0603]  (hidden comment: Capacitor)
C132  ValueDisplayed: 0.22uF  [0603]  (hidden comment: Capacitor)
C133  ValueDisplayed: 0.1uF  [0603]  (hidden comment: Capacitor)
C134  ValueDisplayed: 1uF  [0603]  (hidden comment: Capacitor)
C135  ValueDisplayed: 0.1uF  [0603]  (hidden comment: Capacitor)
C136  ValueDisplayed: 1uF  [0603]  (hidden comment: Capacitor)
C137  ValueDisplayed: 0.01uF  [0603]  (hidden comment: Capacitor)
C138  ValueDisplayed: 1uF  [0603]  (hidden comment: Capacitor)
C139  ValueDisplayed: 0.01uF  [0603]  (hidden comment: Capacitor)
C140  ValueDisplayed: 0.01uF  [0603]  (hidden comment: Capacitor)
C141  ValueDisplayed: 1uF  [0603]  (hidden comment: Capacitor)
C142  ValueDisplayed: 1500pF  [0603]  (hidden comment: Capacitor)
C143  ValueDisplayed: 3900pF  [0603]  (hidden comment: GRM188R72A392KA01D)
C144  ValueDisplayed: 1500pF  [0603]  (hidden comment: Capacitor)
C145  ValueDisplayed: 1uF  [0603]  (hidden comment: Capacitor)
C146  ValueDisplayed: 0.1uF  [0603]  (hidden comment: Capacitor)
C147  ValueDisplayed: 2700pF  [0603]  (hidden comment: Capacitor)
C148  ValueDisplayed: 2700pF  [0603]  (hidden comment: Capacitor)
C149  ValueDisplayed: 10pF  [0603]  (hidden comment: Capacitor)
C150  ValueDisplayed: 1500pF  [0603]  (hidden comment: Capacitor)
C151  ValueDisplayed: 3900pF  [0603]  (hidden comment: GRM188R72A392KA01D)
C152  ValueDisplayed: 20pF  [0603]  (hidden comment: GRM1885C1H200JA01D)
C153  ValueDisplayed: 20pF  [0603]  (hidden comment: GRM1885C1H200JA01D)
C154  ValueDisplayed: 1500pF  [0603]  (hidden comment: Capacitor)
C155  ValueDisplayed: 1uF  [0603]  (hidden comment: Capacitor)
C156  ValueDisplayed: 1uF  [0603]  (hidden comment: Capacitor)
C157  ValueDisplayed: 1000pF  [0603]  (hidden comment: Capacitor)
C158  ValueDisplayed: 100uF  [1206_190]  (hidden comment: Capacitor)
C159  ValueDisplayed: 100uF  [1206_190]  (hidden comment: Capacitor)
C160  ValueDisplayed: 1uF  [0603]  (hidden comment: Capacitor)
C161  ValueDisplayed: 1uF  [0603]  (hidden comment: Capacitor)
J19  PRPC008DAAN-RC  [Sullins_xxxC008DAAN]
R111  ValueDisplayed: 1.50k  [0603]  (hidden comment: RC0603FR-071K5L)
R112  ValueDisplayed: 1.50k  [0603]  (hidden comment: RC0603FR-071K5L)
R113  ValueDisplayed: 49.9  [0603]  (hidden comment: Resistor)
R114  ValueDisplayed: 1.50k  [0603]  (hidden comment: RC0603FR-071K5L)
R115  ValueDisplayed: 49.9  [0603]  (hidden comment: Resistor)
R116  ValueDisplayed: 100k  [0603]  (hidden comment: Resistor)
R117  ValueDisplayed: 1.50k  [0603]  (hidden comment: RC0603FR-071K5L)
R118  ValueDisplayed: 100  [0603]  (hidden comment: Resistor)
R119  ValueDisplayed: 100  [0603]  (hidden comment: Resistor)
R120  ValueDisplayed: 499  [0603]  (hidden comment: Resistor)
R121  ValueDisplayed: 100k  [0603]  (hidden comment: Resistor)
R122  ValueDisplayed: 100k  [0603]  (hidden comment: Resistor)
R123  ValueDisplayed: 100k  [0603]  (hidden comment: Resistor)
R124  ValueDisplayed: 1.50k  [0603]  (hidden comment: RC0603FR-071K5L)
R125  ValueDisplayed: 100  [0603]  (hidden comment: Resistor)
R126  ValueDisplayed: 3.30k  [0603]  (hidden comment: RC0603FR-073K3L)
R127  ValueDisplayed: 100  [0603]  (hidden comment: Resistor)
R128  ValueDisplayed: 49.9  [0603]  (hidden comment: Resistor)
R129  ValueDisplayed: 3.30k  [0603]  (hidden comment: RC0603FR-073K3L)
R130  ValueDisplayed: 49.9  [0603]  (hidden comment: Resistor)
R131  ValueDisplayed: 100k  [0603]  (hidden comment: Resistor)
R132  ValueDisplayed: 1.50k  [0603]  (hidden comment: RC0603FR-071K5L)
R133  ValueDisplayed: 0  [0603]  (hidden comment: Resistor)
R134  ValueDisplayed: 1.00  [0603]  (hidden comment: Resistor)
R135  ValueDisplayed: 0  [0603]  (hidden comment: Resistor)
R136  ValueDisplayed: 0  [0603]  (hidden comment: Resistor)
R137  ValueDisplayed: 1.00M  [0603]  (hidden comment: Resistor)
R138  ValueDisplayed: 1.00k  [0603]  (hidden comment: Resistor)
S1  Switch_PushButton  [SW_TL1015AF160QG]  (value not drawn)
U19  THS4561IDGKR  [DGK0008A_N]
U20  THS4561IDGKR  [DGK0008A_N]
U21  ADS131A04IPBSR  [PBS0032A_L]
U22  TI-REF5025DGK8  [DGK0008A_N]  (part A of 2)
VREF_ADC  Pogo Pad  [PogoPad]  (value not drawn)  (no BOM)
Y1  XTAL_4P_13_G24  [CTS_407]  (value not drawn)

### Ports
IBAT, SPI_CS, SPI_DONE, SPI_DRDY, SPI_MISO, SPI_MOSI, SPI_SCLK, V5.0_DAQ, VBAT

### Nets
-0.2V: U19.6(VS-) U20.6(VS-)
AGND: C131.2 C132.2 C133.2 C134.2 C135.2 C136.2 C137.2 C138.2 C139.2 C140.2 C141.2 C145.1 C146.1 C149.1 C152.2 C153.2 C155.2 C156.2 C157.2 C158.2 C159.2 C160.2 C161.2 J19.13 J19.14 J19.15 J19.16 R112.1 R126.1 R138.1 S1.2 U21.5(AIN3N) U21.6(AIN3P) U21.7(AIN4N) U21.8(AIN4P) U21.10(AVSS) U21.11(VNCP) U21.13(VREFN) U21.27(GND) U21.31(M1) U21.32(M2) U22.4(GND) Y1.2(GND) Y1.4(GND)
AVDD: C133.1 C134.1 C135.1 C136.1 C137.1 C138.1 C160.1 R116.2 R131.2 U19.3(VS+) U20.3(VS+) U21.9(AVDD) U22.2(VIN) ; port V5.0_DAQ
DVDD_3.3V: C139.1 C140.1 C141.1 R120.2 R121.2 R122.2 R123.2 U21.15(IOVDD) U21.16(RESV) U21.29(IOVDD)
Vocm1: C131.1 U19.2(VOCM)
Vocm2: C132.1 U20.2(VOCM)
ADC_SPI_CS: J19.5 U21.23(~{CS})
ADC_SPI_DONE: J19.11 R123.1 U21.18(~{DONE})
ADC_SPI_DRDY: J19.9 U21.19(~{DRDY})
ADC_SPI_MISO: J19.1 R122.1 U21.21(DOUT)
ADC_SPI_MOSI: J19.3 U21.20(DIN)
ADC_SPI_SCLK: J19.7 R138.2 U21.22(SCLK)
IBAT: R114.1 ; port IBAT
SPI_CS: J19.6 ; port SPI_CS
SPI_DONE: J19.12 ; port SPI_DONE
SPI_DRDY: J19.10 ; port SPI_DRDY
SPI_MISO: J19.2 ; port SPI_MISO
SPI_MOSI: J19.4 ; port SPI_MOSI
SPI_SCLK: J19.8 ; port SPI_SCLK
VBAT: R129.1 ; port VBAT
NetC142_1: C142.1 C143.1 R111.1 R112.2 U19.1(VIN-)
NetC142_2: C142.2 R113.1 U19.4(VOUT+)
NetC143_2: C143.2 C144.1 R114.2 R117.1 U19.8(VIN+)
NetC144_2: C144.2 R115.1 U19.5(VOUT-)
NetC145_2: C145.2 C146.2 U21.12(VREFP)
NetC147_1: C147.1 R118.2 U21.1(AIN1N)
NetC147_2: C147.2 R119.2 U21.2(AIN1P)
NetC148_1: C148.1 R125.2 U21.3(AIN2N)
NetC148_2: C148.2 R127.2 U21.4(AIN2P)
NetC149_2: C149.2 R121.1 S1.1 U21.17(~{RESET})
NetC150_1: C150.1 C151.1 R124.1 R126.2 U20.1(VIN-)
NetC150_2: C150.2 R128.1 U20.4(VOUT+)
NetC151_2: C151.2 C154.1 R129.2 R132.1 U20.8(VIN+)
NetC152_1: C152.1 R135.2 Y1.1
NetC153_1: C153.1 R136.1 Y1.3
NetC154_2: C154.2 R130.1 U20.5(VOUT-)
NetC155_1: C155.1 R133.2 U21.14(REFEXT)
NetC156_1: C156.1 U21.28(CAP)
NetC157_1: C157.1 U22.5(TRIM/NR)
NetC158_1: C158.1 C159.1 R133.1 R134.2 U22.6(VOUT) VREF_ADC.1
NetC161_1: C161.1 R134.1
NetR111_2: R111.2 R113.2 R119.1
NetR115_2: R115.2 R117.2 R118.1
NetR116_1: R116.1 U19.7(~{PD})
NetR120_1: R120.1 U21.30(M0)
NetR124_2: R124.2 R127.1 R128.2
NetR125_1: R125.1 R130.2 R132.2
NetR131_1: R131.1 U20.7(~{PD})
NetR135_1: R135.1 R137.2 U21.25(CLKIN/XTAL1)
NetR136_2: R136.2 R137.1 U21.26(XTAL2)

Not connected (* = marked no-connect by the designer): U21 24(NC); U22 3(TEMP)

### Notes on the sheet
- (near R120) M0:
  Install pull-up resistor to IOVDD for Asynchronous Interrupt Mode
  Uninstall pull-up resistor to leave M0 floating for Synchronous Slave Mode

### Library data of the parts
C131 C132 = CMP-0006903-4: CAP, CERM, 0.22 uF, 16 V, +/- 10%, X7R, 0603; PartNumber: C0603C224K4RACTU; Manufacturer: Kemet; Polarized: N; Value: 0.22uF; U/M: EA; Cap_F: 220nF; Value1: Unknown; VDC_V: 16V; TaMin_C: -55°C; TaMax_C: 125°C; AEC Category: Q200; SizeArea_mm2: 1.28; SizeAreaWB_mm2: 4.68; SizeX_mm: 1.6; SizeY_mm: 0.8; SizeZ_mm: 1
C133 C135 C146 = CMP-0006752-5: as C96 on sheet SV601272A-Analog
C134 C136 C138 C141 C145 C155 C156 C160 C161 = CMP-0007405-4: CAP, CERM, 1 uF, 25 V, +/- 10%, X7R, 0603; PartNumber: GRM188R71E105KA12D; Manufacturer: MuRata; Polarized: N; Value: 1uF; U/M: EA; Cap_F: 1µF; Value1: Unknown; VDC_V: 25V; TaMin_C: -55°C; TaMax_C: 125°C; AEC Category: Q200; SizeArea_mm2: 1.28; SizeAreaWB_mm2: 4.68; SizeX_mm: 1.6; SizeY_mm: 0.8; SizeZ_mm: 1
C137 C139 C140 = CMP-0006727-4: CAP, CERM, 0.01 uF, 100 V, +/- 10%, X7R, 0603; PartNumber: 06031C103KAT2A; Manufacturer: AVX; Polarized: N; Value: 0.01uF; U/M: EA; Cap_F: 10nF; ESR_ohm: 0.098; Value1: 0.098 ohm; VDC_V: 100V; TaMin_C: -55°C; TaMax_C: 125°C; AEC Category: Q200; SizeArea_mm2: 1.28; SizeAreaWB_mm2: 4.68; SizeX_mm: 1.6; SizeY_mm: 0.8; SizeZ_mm: 1
C142 C144 C150 C154 = CMP-0006732-4: CAP, CERM, 1500 pF, 100 V, +/- 5%, X7R, 0603; PartNumber: 06031C152JAT2A; Manufacturer: AVX; Polarized: N; Value: 1500pF; U/M: EA; Cap_F: 1.5nF; ESR_ohm: 2.29d; Value1: 0.229 ohm; VDC_V: 100V; TaMin_C: -55°C; TaMax_C: 125°C; AEC Category: Q200; SizeArea_mm2: 1.28; SizeAreaWB_mm2: 4.68; SizeX_mm: 1.6; SizeY_mm: 0.8; SizeZ_mm: 1
C143 C151 = CMP-0007481-5: CAP, CERM, 3900 pF, 100 V, +/- 10%, X7R, 0603; Manufacturer: MuRata; TaMin_C: -55°C; Polarized: N; SizeAreaWB_mm2: 4.68; Value1: Unknown; U/M: EA; Value: 3900pF; TaMax_C: 125°C; SizeZ_mm: 1; SizeX_mm: 1.6; SizeY_mm: 0.8; Value2: 100V; SizeArea_mm2: 1.28; CompType: Capacitor; Cap_F: 3.9nF; AEC Category: Q200
C147 C148 = CMP-0007204-4: CAP, CERM, 2700 pF, 50 V, +/- 5%, C0G/NP0, 0603; PartNumber: GRM1885C1H272JA01D; Manufacturer: MuRata; Polarized: N; Value: 2700pF; U/M: EA; Cap_F: 2.7nF; Value1: Unknown; VDC_V: 50V; TaMin_C: -55°C; TaMax_C: 125°C; AEC Category: Q200; SizeArea_mm2: 1.28; SizeAreaWB_mm2: 4.68; SizeX_mm: 1.6; SizeY_mm: 0.8; SizeZ_mm: 1
C149 = CMP-0006761-4: CAP, CERM, 10 pF, 50 V, +/- 5%, C0G/NP0, 0603; PartNumber: 06035A100JAT2A; Manufacturer: AVX; Polarized: N; Value: 10pF; U/M: EA; ESR_ohm: 4.03d; Value1: 0.403 ohm; VDC_V: 50V; TaMin_C: -55°C; TaMax_C: 125°C; AEC Category: Q200; SizeArea_mm2: 1.28; SizeAreaWB_mm2: 4.68; SizeX_mm: 1.6; SizeY_mm: 0.8; SizeZ_mm: 1
C152 C153 = CMP-0007193-4: CAP, CERM, 20 pF, 50 V, +/- 5%, C0G/NP0, 0603; Manufacturer: MuRata; TaMin_C: -55°C; Polarized: N; SizeAreaWB_mm2: 4.68; Value1: Unknown; U/M: EA; Value: 20pF; TaMax_C: 125°C; SizeZ_mm: 1; SizeX_mm: 1.6; SizeY_mm: 0.8; Value2: 50V; SizeArea_mm2: 1.28; CompType: Capacitor; AEC Category: Q200
C157 = CMP-0006723-4: CAP, CERM, 1000 pF, 100 V, +/- 5%, X7R, 0603; PartNumber: 06031C102JAT2A; Manufacturer: AVX; Polarized: N; Value: 1000pF; U/M: EA; Cap_F: 1nF; ESR_ohm: 2.76d; Value1: 0.276 ohm; VDC_V: 100V; TaMin_C: -55°C; TaMax_C: 125°C; AEC Category: Q200; SizeArea_mm2: 1.28; SizeAreaWB_mm2: 4.68; SizeX_mm: 1.6; SizeY_mm: 0.8; SizeZ_mm: 1
C158 C159 = CMP-0008649-2: CAP, CERM, 100 uF, 10 V, +/- 20%, X5R, 1206_190; PartNumber: C3216X5R1A107M160AC; Manufacturer: TDK; Polarized: N; Value: 100uF; U/M: EA; Cap_F: 100µF; ESR_ohm: 2.838m; Value1: 0.002838 ohm; VDC_V: 10V; IRMS_A: 4.30694A; TaMin_C: -55°C; TaMax_C: 85°C; AEC Category: Q200; SizeArea_mm2: 5.12; SizeAreaWB_mm2: 10.92; SizeX_mm: 3.2; SizeY_mm: 1.6; SizeZ_mm: 1.9
J19 = CMP-0054590-1: Header, 2.54mm, 8x2, Gold, TH; Manufacturer: Sullins Connector Solutions; CNHeader: TRUE; Shrouded: N; Gender: Male; Row_Count: 2; RowSpacing_mm: 2.54; CT: FALSE
R111 R112 R114 R117 R124 = CMP-0022883-3: RES, 1.50 k, 1%, 0.1 W, 0603; Manufacturer: Yageo America; Power_W: 100mW; TempCo: 200 ppm/C; Value_Code: 1k50; U/M: EA; Value: 1.50k; EIA_Code: E96; Res_ohm: 1.5k; SizeX_mm: 1.6; SizeY_mm: 0.8; SizeZ_mm: 1; Value2: 0.1W; SizeArea_mm2: 1.28; CompType: Resistor; VDC_V: 150V; AEC Category: Q200
R113 R115 R128 R130 = CMP-0022448-4: RES, 49.9, 1%, 0.1 W, AEC-Q200 Grade 0, 0603; PartNumber: CRCW060349R9FKEA; Manufacturer: Vishay-Dale; Value: 49.9; Value_Code: 49R9; Power_W: 100mW; Value2: 0.1W; VDC_V: 75V; TempCo: 100 ppm/C; EIA_Code: E96; AEC Category: Q200; AEC Qualified: Y; AEC Grade: 0; SizeArea_mm2: 1.28; SizeX_mm: 1.6; SizeY_mm: 0.8; SizeZ_mm: 1
R116 R121-R123 R131 = CMP-0021990-4: RES, 100 k, 1%, 0.1 W, AEC-Q200 Grade 0, 0603; PartNumber: CRCW0603100KFKEA; Manufacturer: Vishay-Dale; Value: 100k; Power_W: 100mW; Value2: 0.1W; VDC_V: 75V; TempCo: 100 ppm/C; EIA_Code: E96; AEC Category: Q200; AEC Qualified: Y; AEC Grade: 0; SizeArea_mm2: 1.28; SizeX_mm: 1.6; SizeY_mm: 0.8; SizeZ_mm: 1
R118 R119 R125 R127 = CMP-0021991-4: RES, 100, 1%, 0.1 W, AEC-Q200 Grade 0, 0603; PartNumber: CRCW0603100RFKEA; Manufacturer: Vishay-Dale; Value: 100; Value_Code: 100R; Power_W: 100mW; Value2: 0.1W; VDC_V: 75V; TempCo: 100 ppm/C; EIA_Code: E96; AEC Category: Q200; AEC Qualified: Y; AEC Grade: 0; SizeArea_mm2: 1.28; SizeX_mm: 1.6; SizeY_mm: 0.8; SizeZ_mm: 1
R120 = CMP-0022446-5: RES, 499, 1%, 0.1 W, AEC-Q200 Grade 0, 0603; PartNumber: CRCW0603499RFKEA; Manufacturer: Vishay-Dale; Value: 499; Value_Code: 499R; Power_W: 100mW; Value2: 0.1W; VDC_V: 75V; TempCo: 100 ppm/C; EIA_Code: E96; AEC Category: Q200; AEC Qualified: Y; AEC Grade: 0; SizeArea_mm2: 1.28; SizeX_mm: 1.6; SizeY_mm: 0.8; SizeZ_mm: 1
R126 R129 = CMP-0023081-3: RES, 3.30 k, 1%, 0.1 W, 0603; Manufacturer: Yageo America; Power_W: 100mW; TempCo: 200 ppm/C; Value_Code: 3k30; U/M: EA; Value: 3.30k; Res_ohm: 3.3k; SizeX_mm: 1.6; SizeY_mm: 0.8; SizeZ_mm: 1; Value2: 0.1W; SizeArea_mm2: 1.28; VDC_V: 150V; AEC Category: Q200
R132 = CMP-0022883-3: RES, 1.50 k, 1%, 0.1 W, 0603; Manufacturer: Yageo America; Power_W: 100mW; TempCo: 200 ppm/C; Value_Code: 1k50; U/M: EA; Value: 1.50k; EIA_Code: E96; Res_ohm: 1.5k; SizeX_mm: 1.6; SizeY_mm: 0.8; SizeZ_mm: 1; Value2: 0.1W; SizeArea_mm2: 1.28; VDC_V: 150V; AEC Category: Q200
R133 R135 R136 = CMP-0025874-3: as R163 on sheet SV601272A-Analog
R134 = CMP-0022170-4: RES, 1.00, 1%, 0.1 W, AEC-Q200 Grade 0, 0603; PartNumber: CRCW06031R00FKEA; Manufacturer: Vishay-Dale; Value: 1.00; Res_ohm: 1; Value_Code: 1R00; Power_W: 100mW; Value2: 0.1W; VDC_V: 75V; TempCo: 100 ppm/C; EIA_Code: E96; AEC Category: Q200; AEC Qualified: Y; AEC Grade: 0; SizeArea_mm2: 1.28; SizeX_mm: 1.6; SizeY_mm: 0.8
R137 = CMP-0022138-4: RES, 1.00 M, 1%, 0.1 W, AEC-Q200 Grade 0, 0603; PartNumber: CRCW06031M00FKEA; Manufacturer: Vishay-Dale; Value: 1.00Meg; Res_ohm: 1M; Value_Code: 1M00; Power_W: 100mW; Value2: 0.1W; VDC_V: 75V; TempCo: 100 ppm/C; EIA_Code: E96; AEC Category: Q200; AEC Qualified: Y; AEC Grade: 0; SizeArea_mm2: 1.28; SizeX_mm: 1.6; SizeY_mm: 0.8; SizeZ_mm: 1
R138 = CMP-0022109-5: RES, 1.00 k, 1%, 0.1 W, AEC-Q200 Grade 0, 0603; PartNumber: CRCW06031K00FKEA; Manufacturer: Vishay-Dale; Value: 1.00k; Res_ohm: 1k; Value_Code: 1k00; Power_W: 100mW; Value2: 0.1W; VDC_V: 75V; TempCo: 100 ppm/C; EIA_Code: E96; AEC Category: Q200; AEC Qualified: Y; AEC Grade: 0; SizeArea_mm2: 1.28; SizeX_mm: 1.6; SizeY_mm: 0.8; SizeZ_mm: 1
S1 = CMP-0002143-3: Switch, Tactile, SPST-NO, 0.05A, 12V, SMT; PartNumber: TL1015AF160QG; Manufacturer: E-Switch; SwitchFunction: Off-Mom; PositionCount: 1; CurrentRating_mA: 50A
U19 U20 = CMP-0074888-1: Low-Power, High Supply Range, 60-MHz, Fully Differential Amplifier, DGK0008A (VSSOP-8); Alternate PartNumber: THS4561IDGKT; Alternate Manufacturer: Texas Instruments; SizeAreaWB_mm2: 35.955; U/M: EA; SizeZ_mm: 1.1; SizeX_mm: 5.05; SizeY_mm: 3.1; SizeArea_mm2: 15.655; CompType: IC
U21 = CMP-0075938-2: 24-Bit, 128kSPS, 4-Ch, Simultaneous Sampling, Delta-Sigma ADC, PBS0032A (TQFP-32); Manufacturer: Texas Instruments; SizeZ_mm: 1.2; SizeX_mm: 7.0; SizeArea_mm2: 49.0; CompType: IC; U/M: EA; SizeAreaWB_mm2: 81.0
U22 = CMP-0032584-1: Low Noise, Very Low Drift, Precision Voltage Reference, -40 to 125 degC, 8-pin MSOP(DGK), Green (RoHS & no Sb/Br); PartNumber: REF5025IDGKR; Manufacturer: Texas Instruments; Initial Accuracy @ 25/deg C(%): 0.05; Iout/Iz(Max)(mA): 10; Iq(Max)(uA): 1000; Rating: Military; SubFamily: Series Voltage Reference; Temp Coeff(Max)(ppm/ degree C): 3; VI(Max)(V): 18; VI(Min)(V): 2.7; VO(V): 2.5
VREF_ADC = PogoPad: as CV on sheet SV601272A-Analog
Y1 = CMP-0004606-3: Crystal, 16.384 MHz, 20 pF, SMD; PartNumber: 407F35E016M3840; Manufacturer: CTS Electrocomponents; TaMin_C: -20°C; TaMax_C: 70°C; Frequency Stability: +/-50ppm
